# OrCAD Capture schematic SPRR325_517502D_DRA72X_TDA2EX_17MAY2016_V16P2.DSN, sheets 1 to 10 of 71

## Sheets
1 SH01 - TITLE PAGE: title: DRA72x/TDA2Ex EVM CPU Board; rev: D; company: TEXAS INSTRUMENTS INCORPORATED; note: 517502
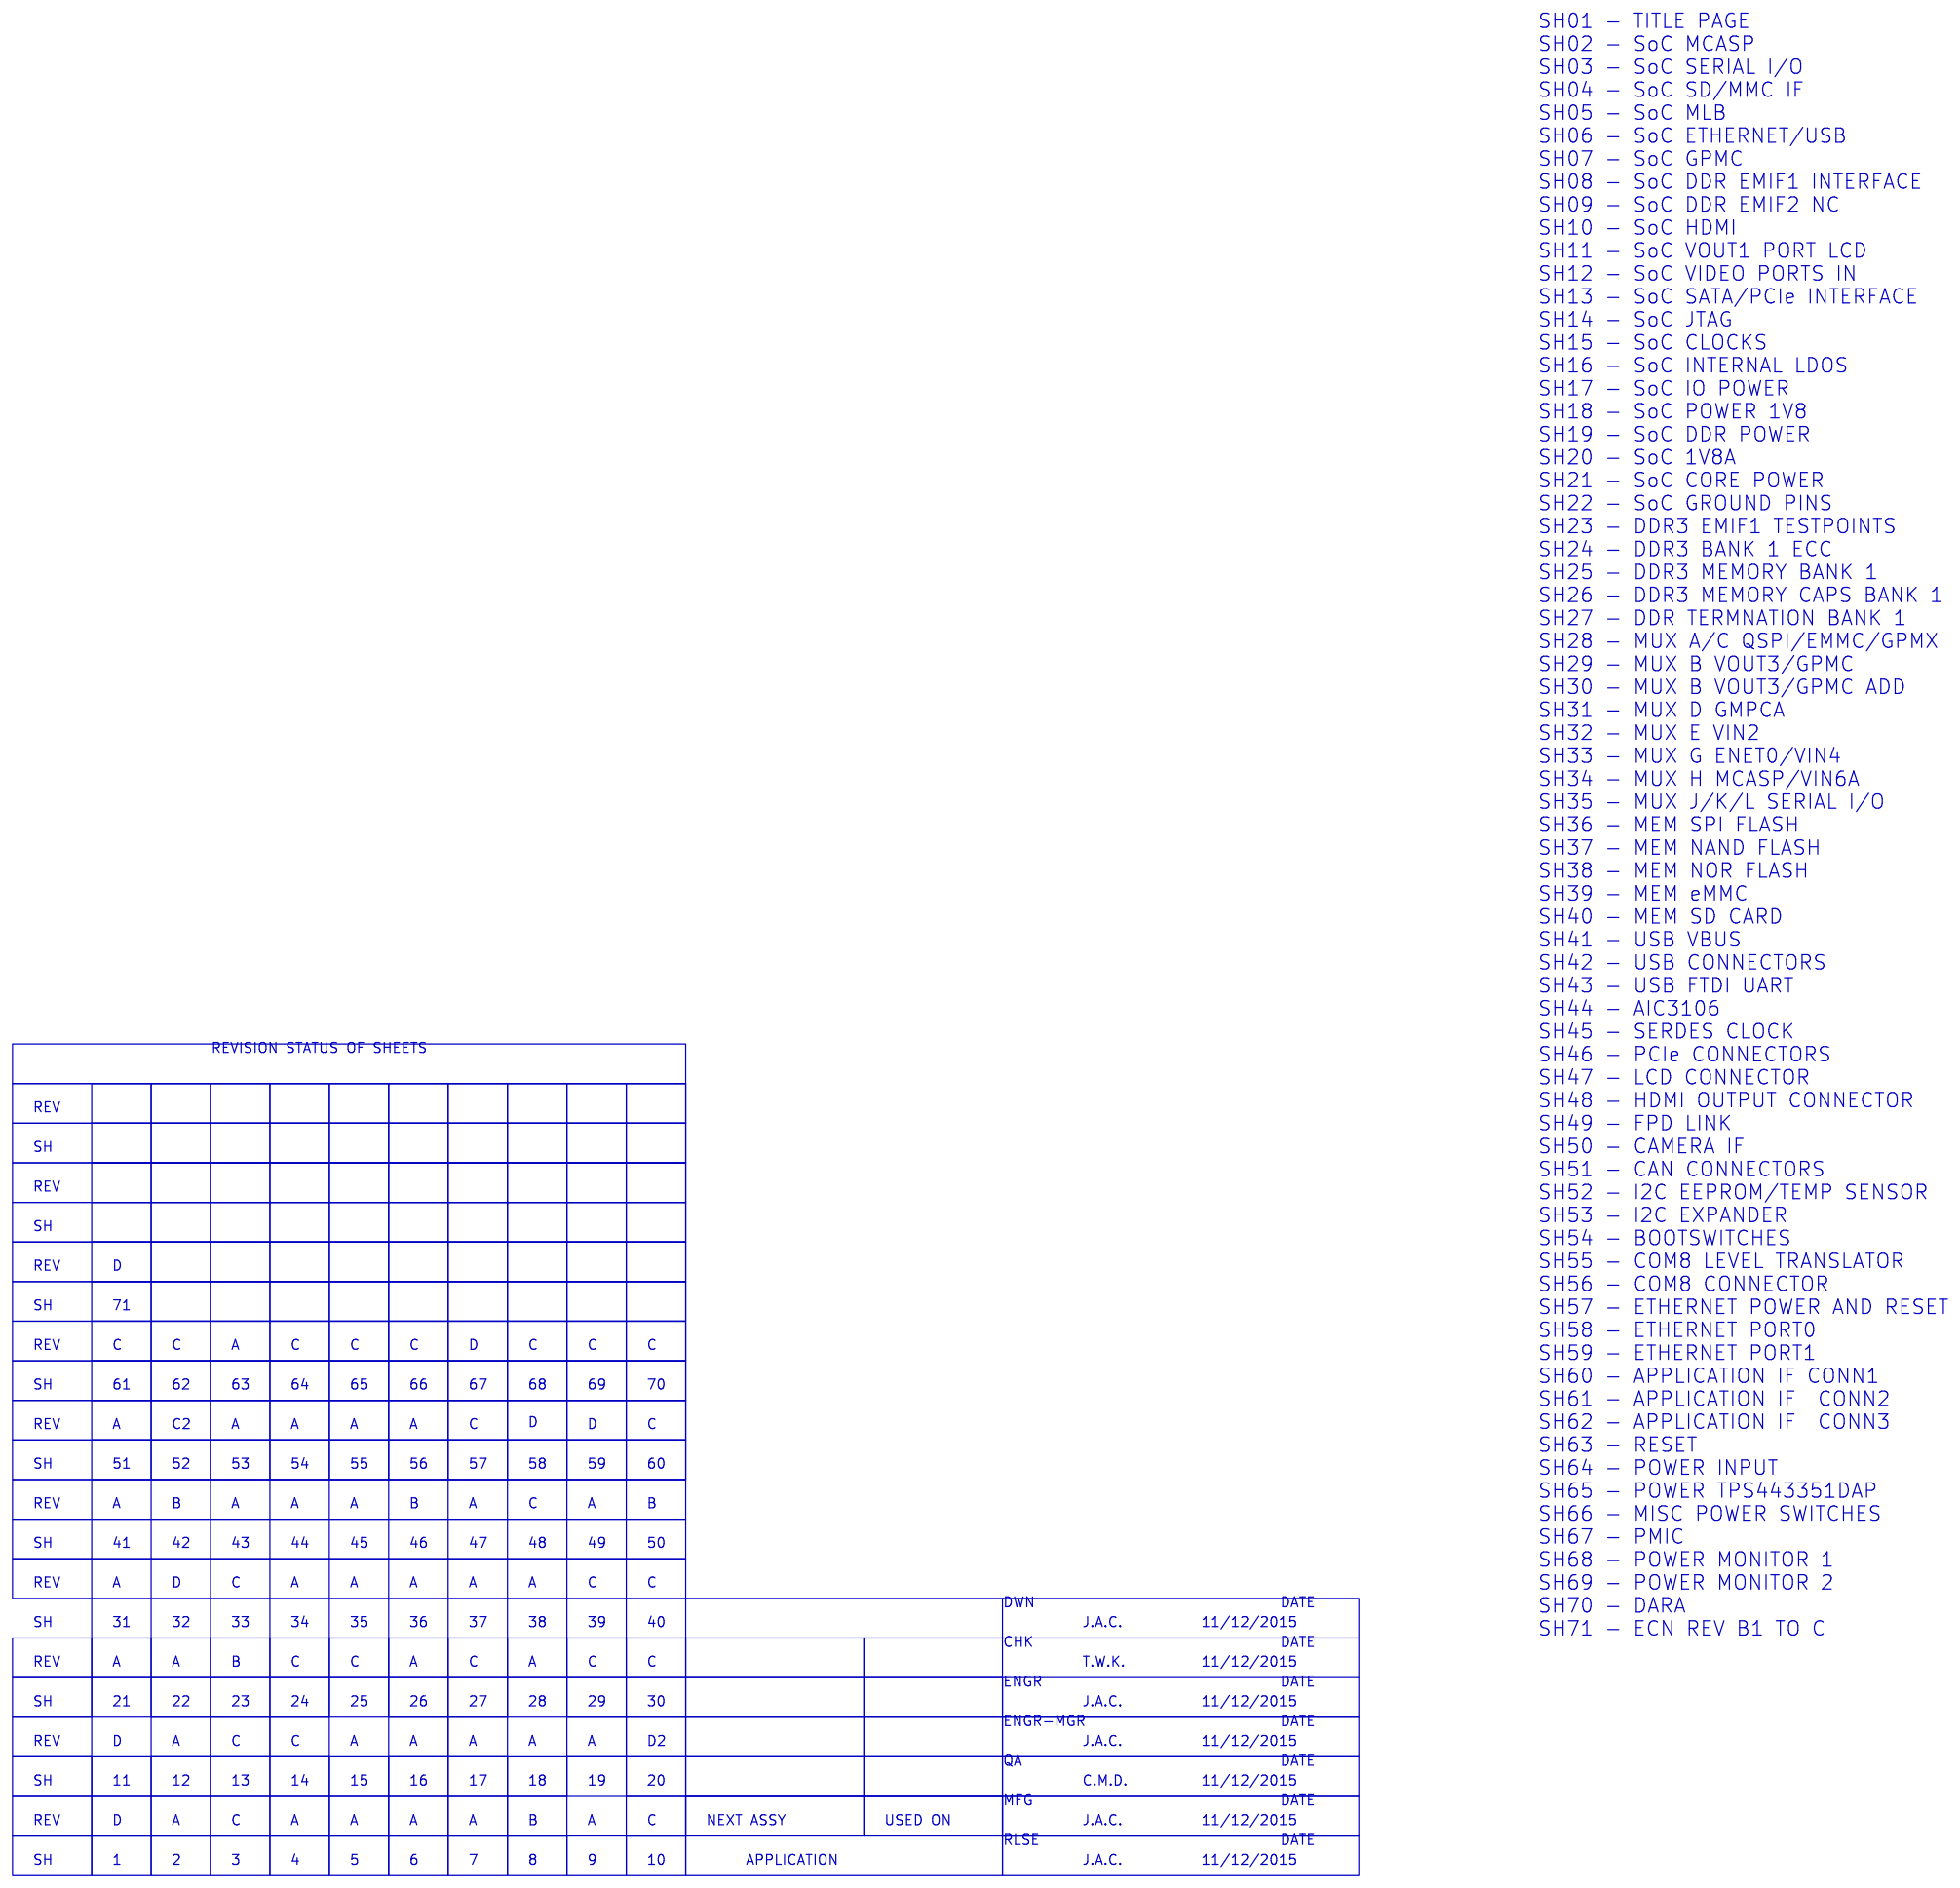
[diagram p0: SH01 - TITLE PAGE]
2 SH02 - SoC MCASP: size B; rev: A
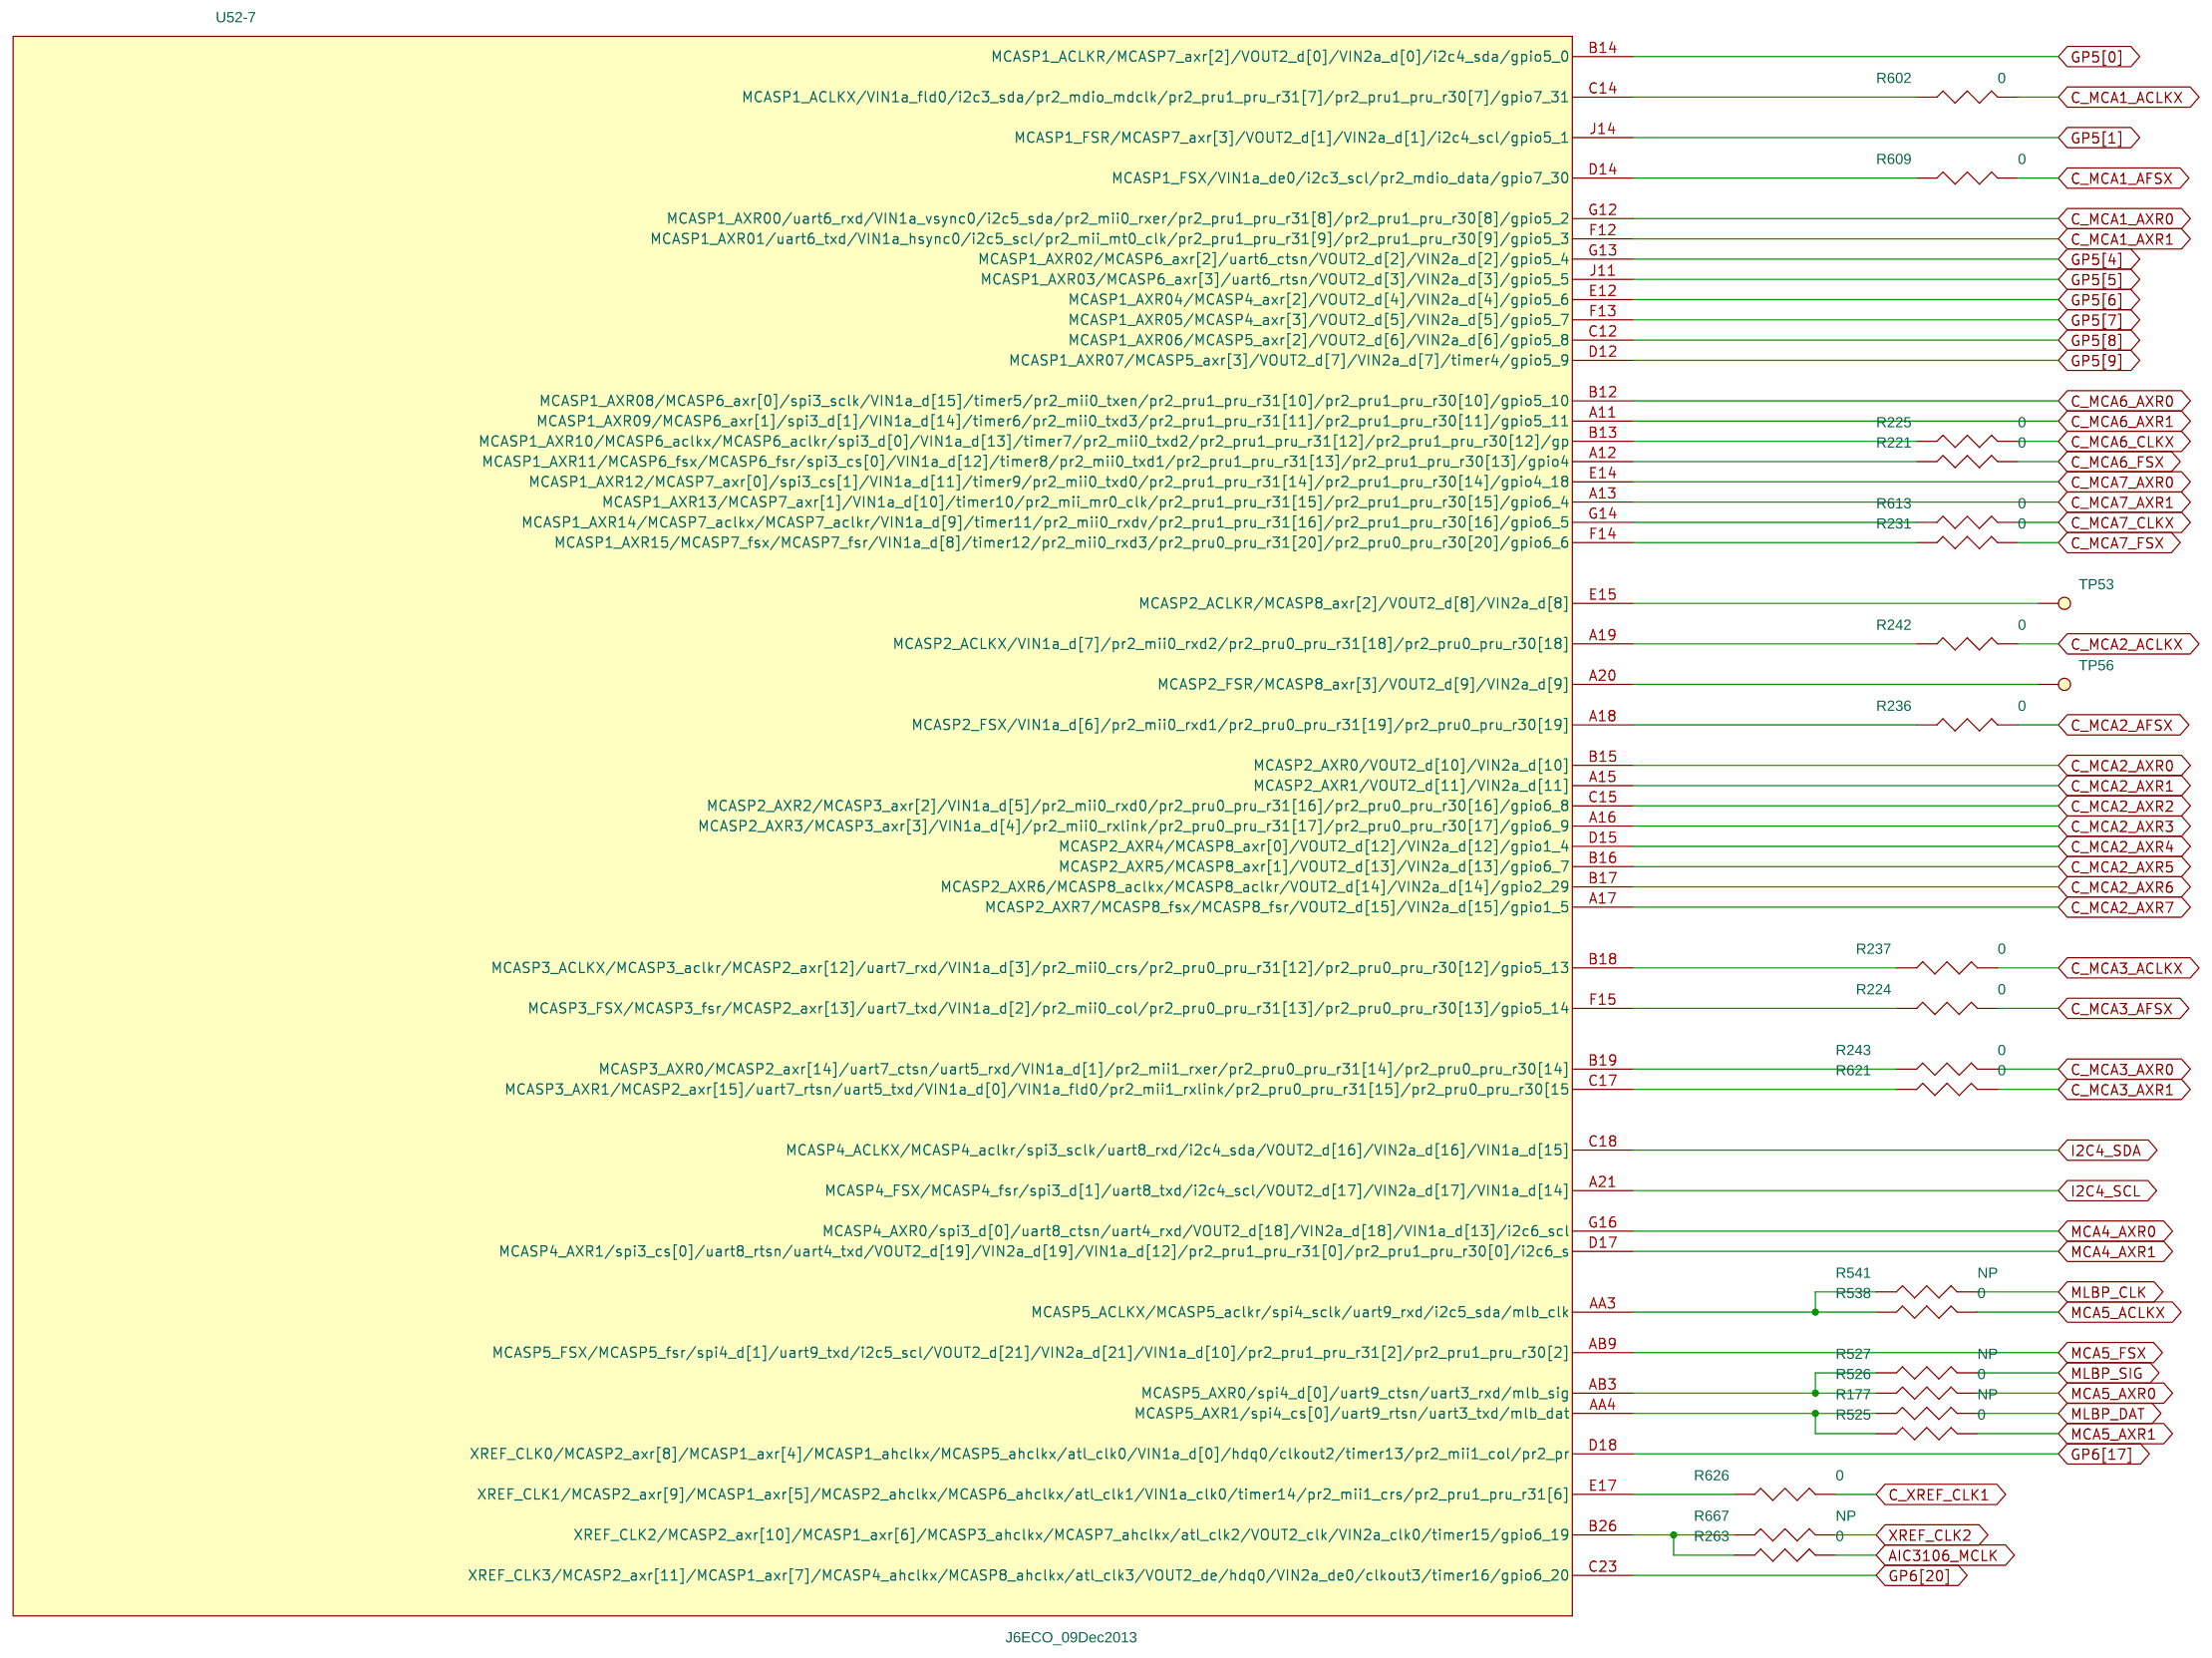
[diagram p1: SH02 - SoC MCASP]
3 SH05 - SoC MLB: size B; rev: A
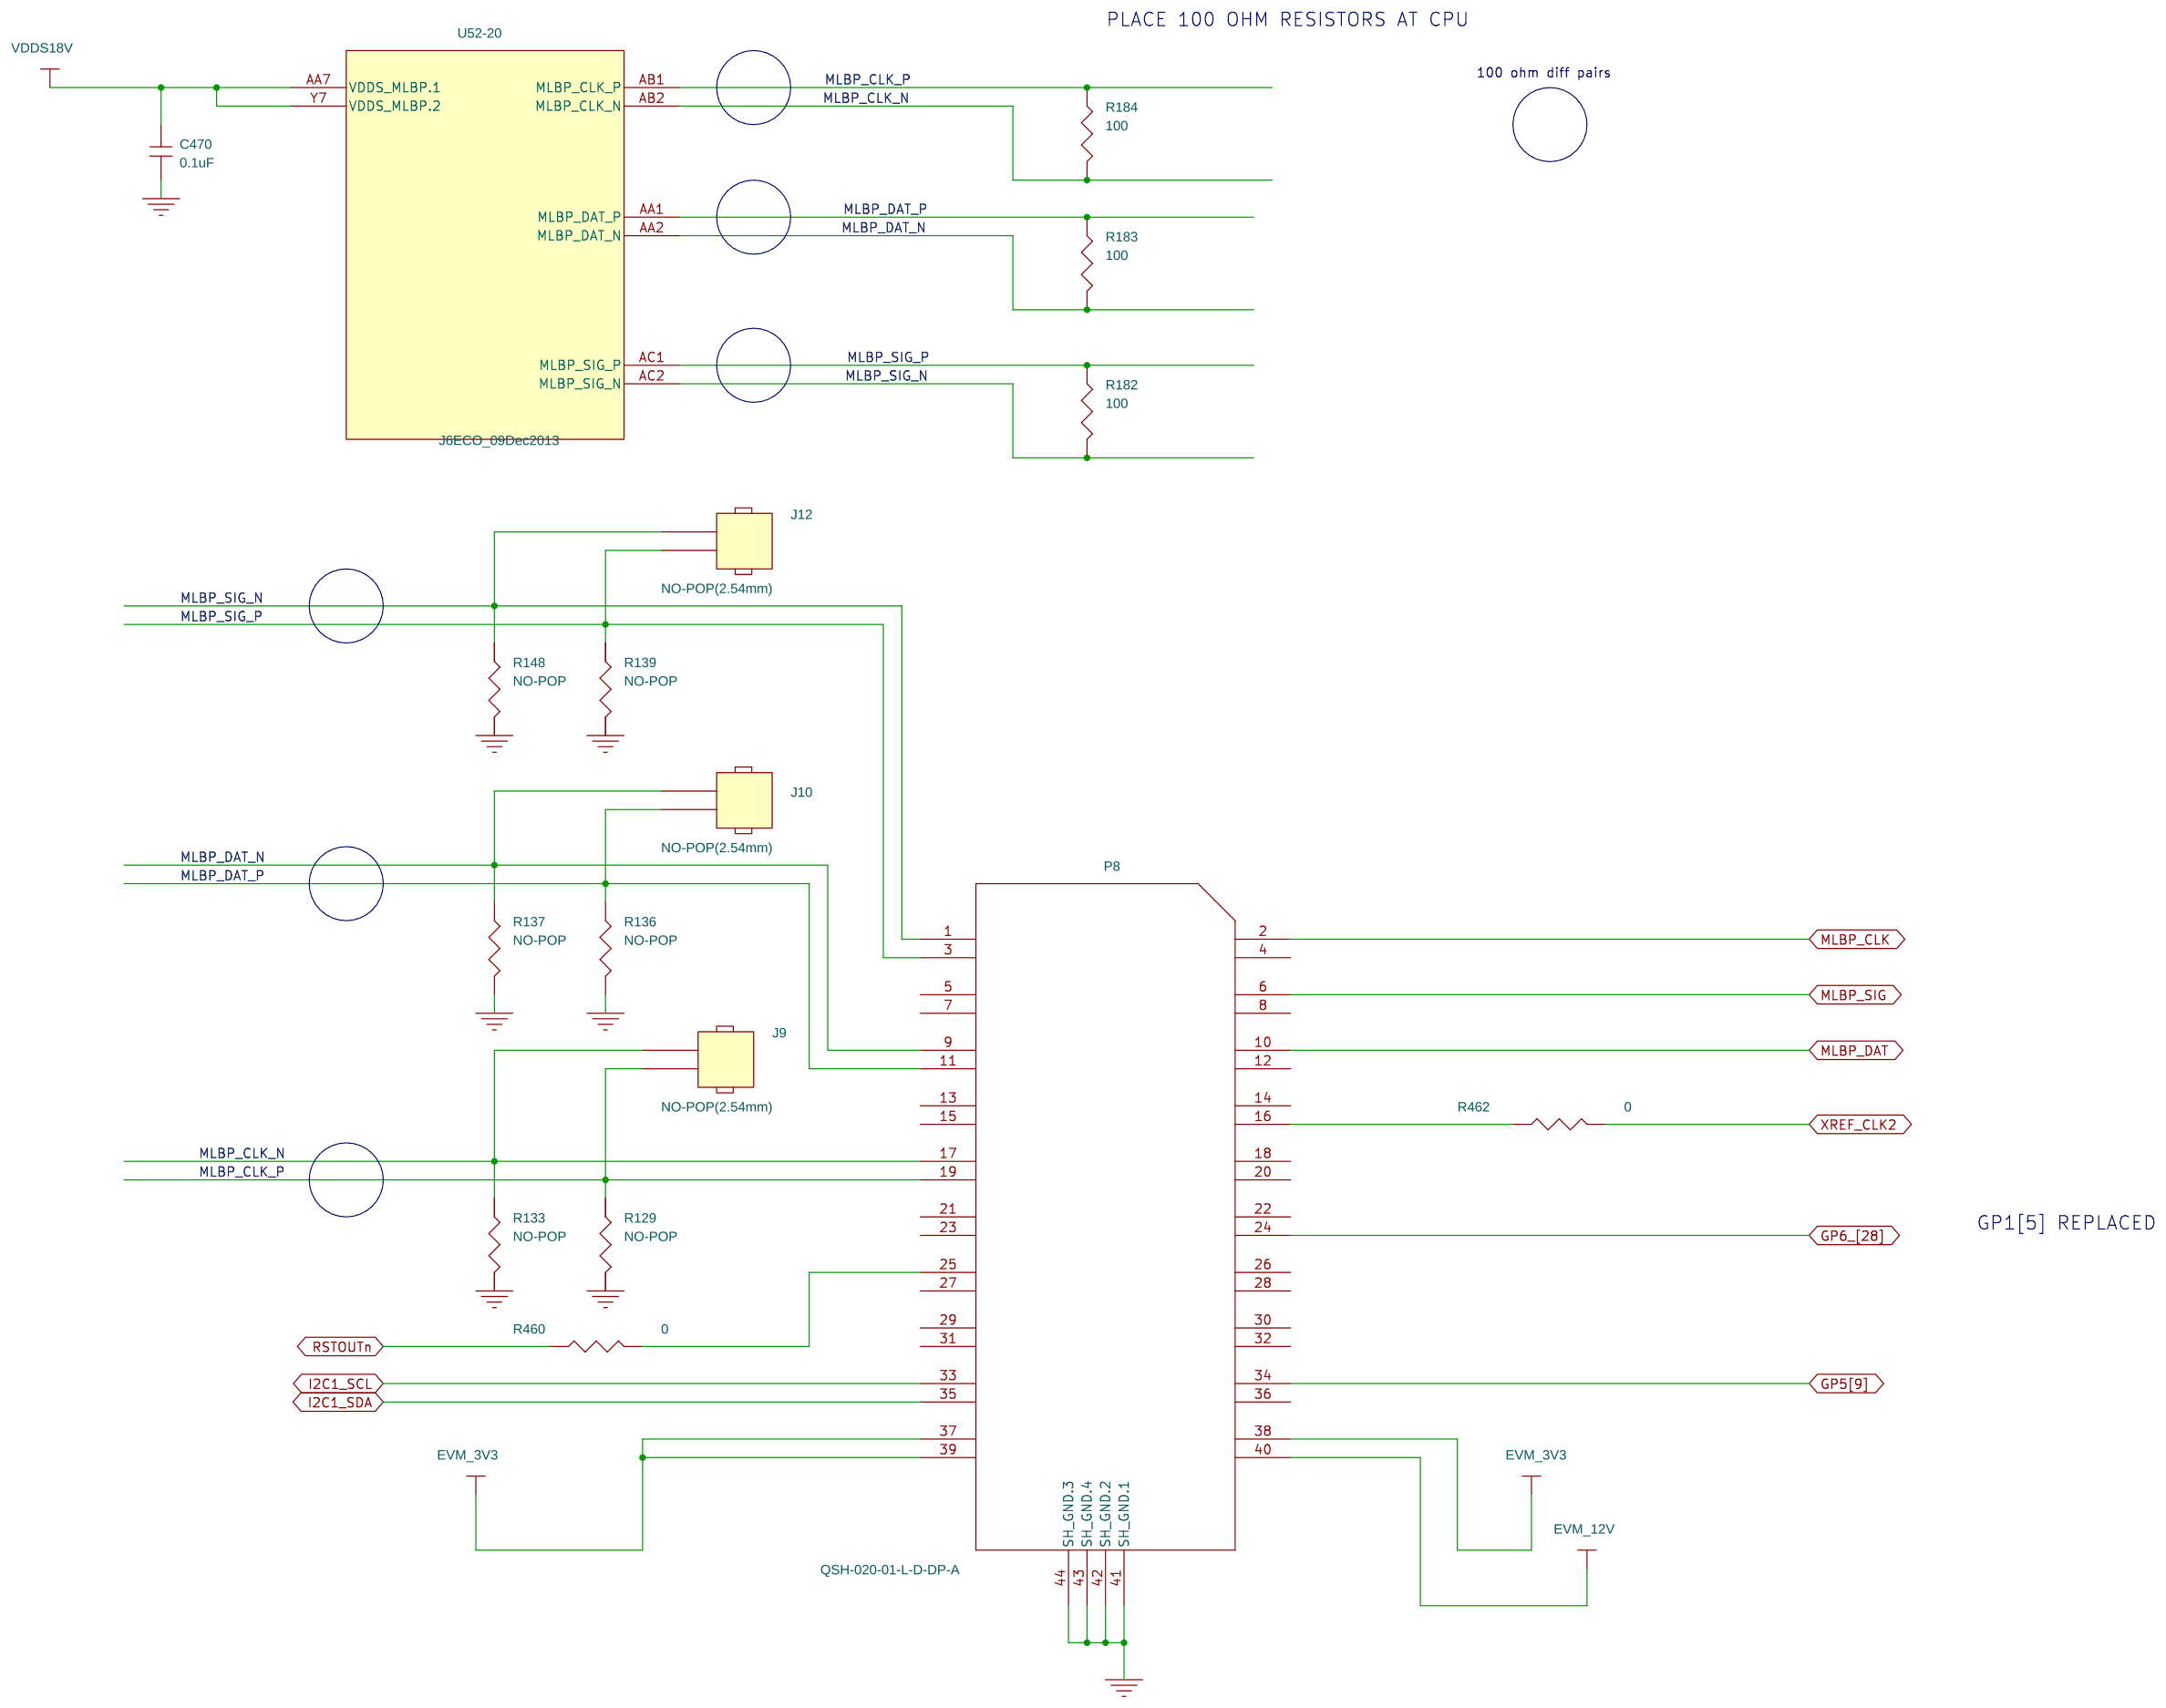
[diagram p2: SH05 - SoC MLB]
4 SH07 - SoC GPMC: size B; rev: A
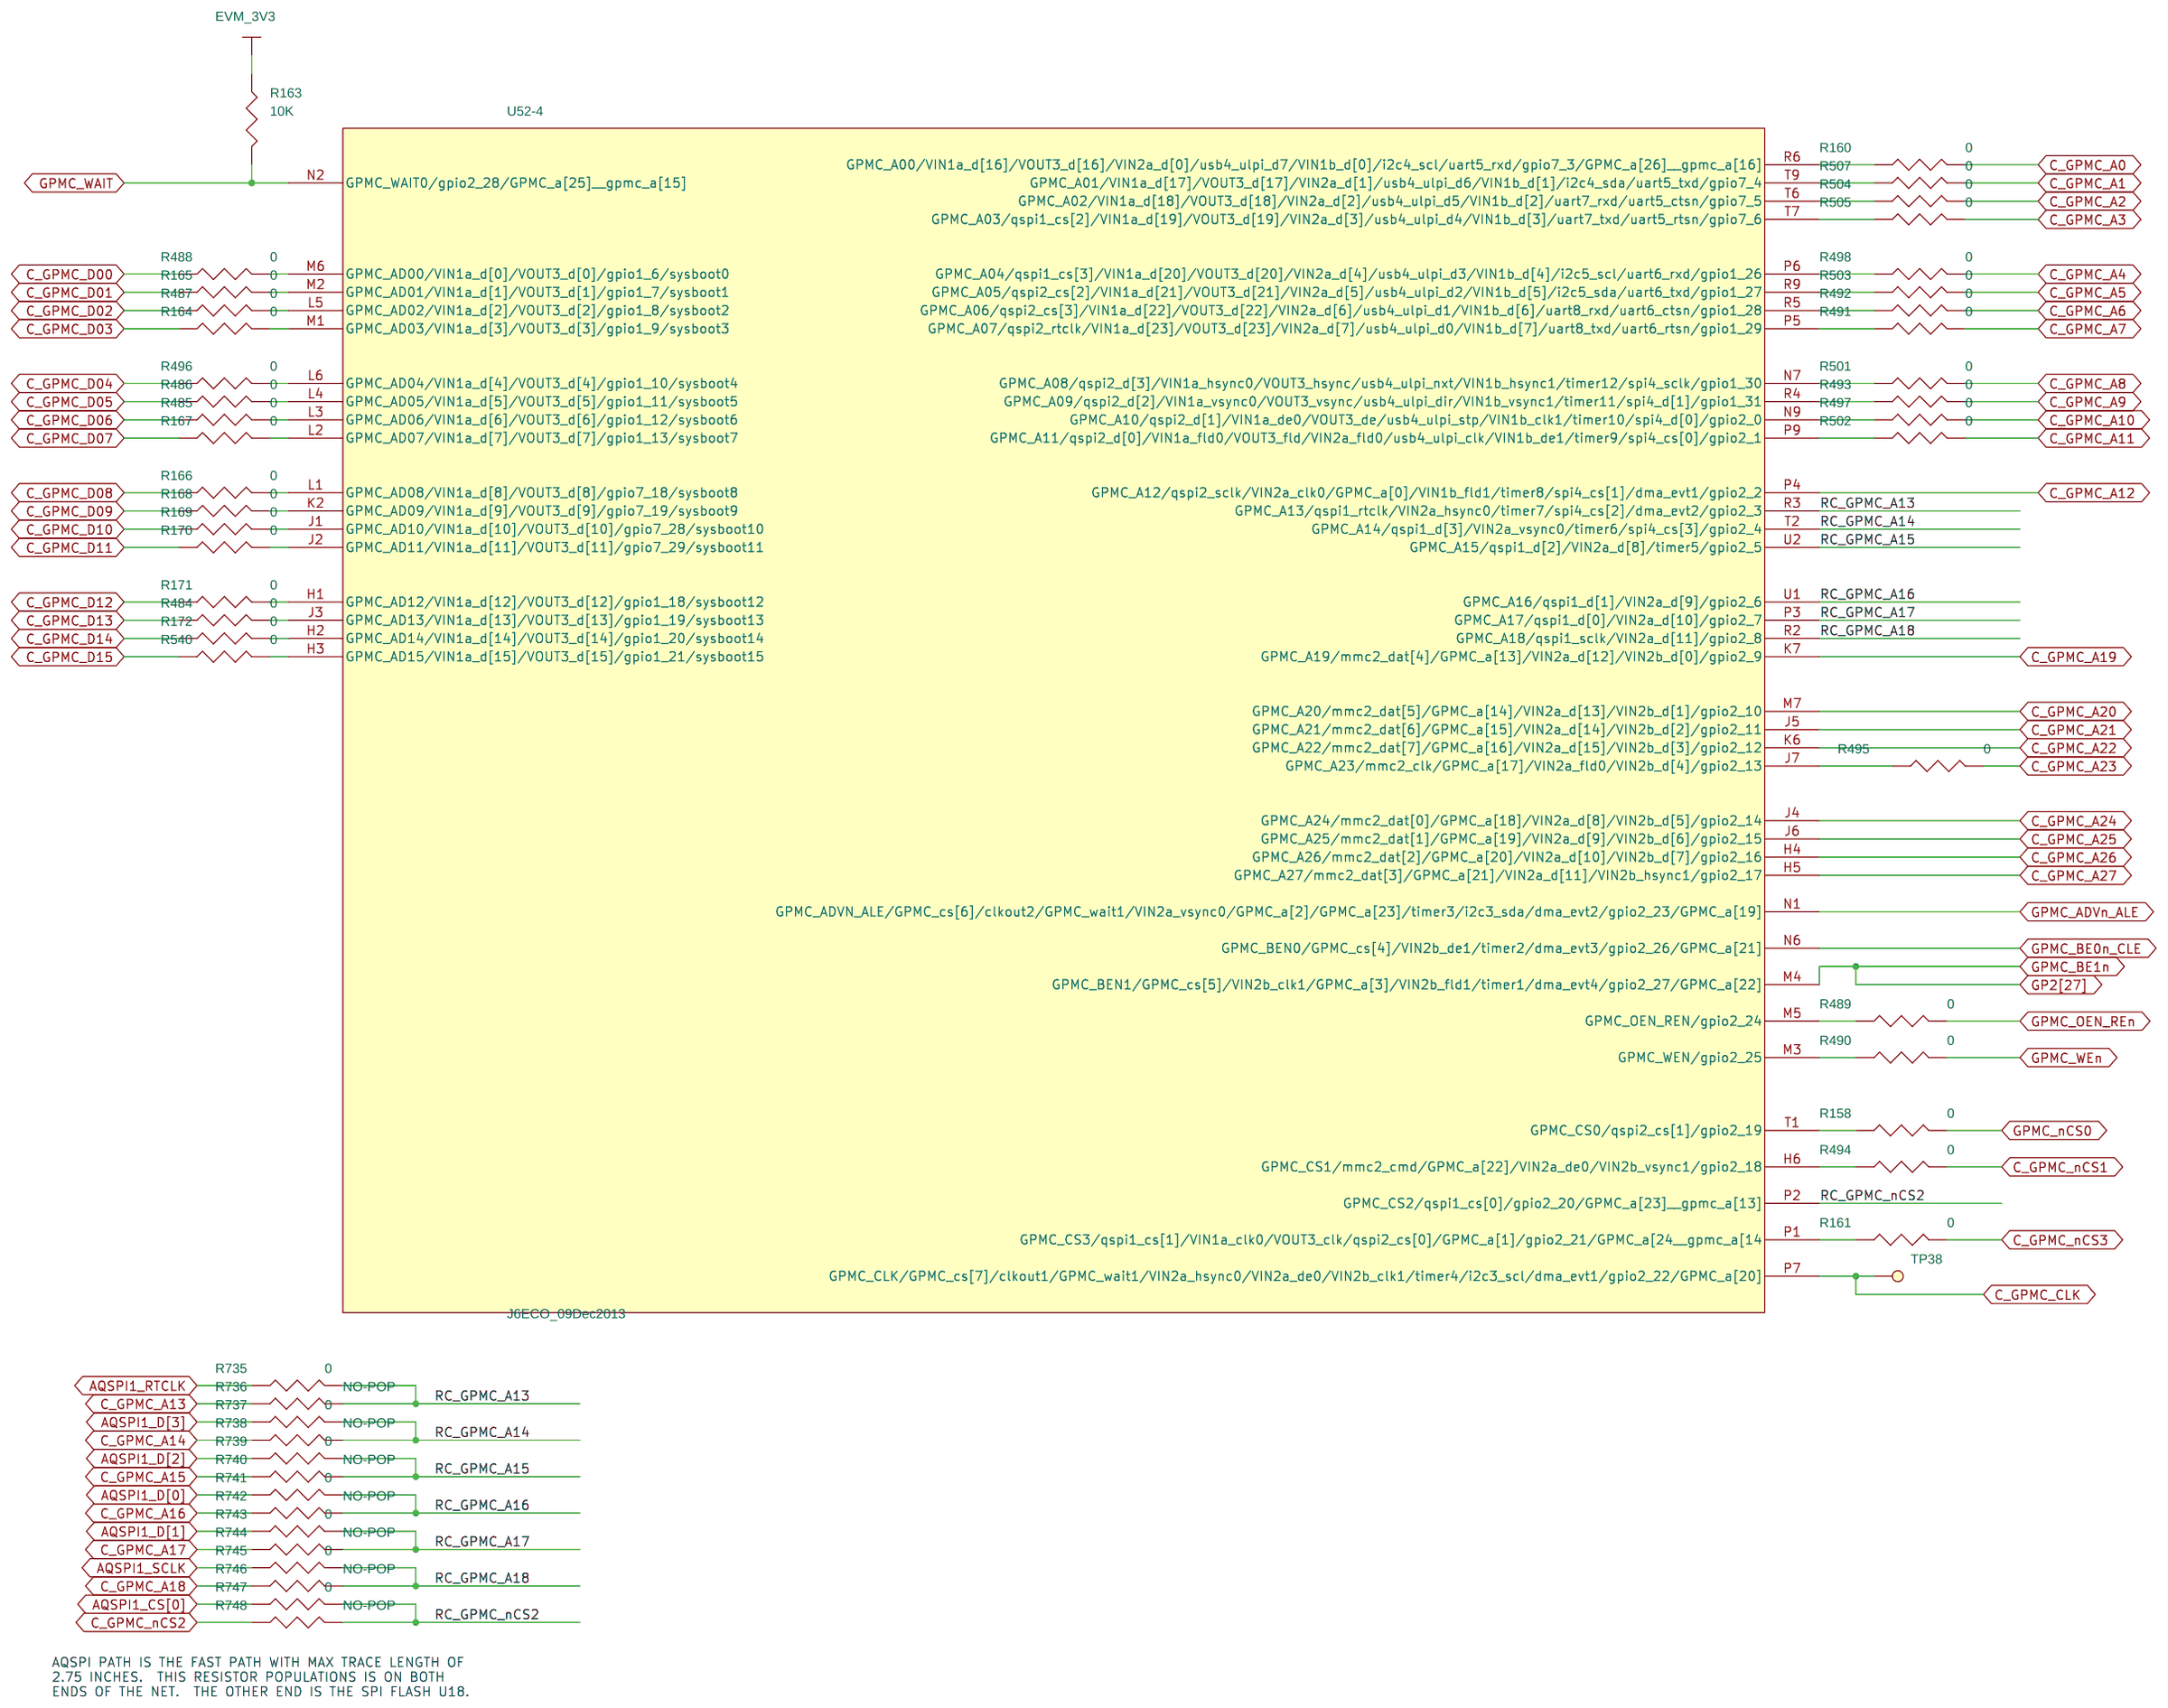
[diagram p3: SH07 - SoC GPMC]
5 SH08 - SoC DDR EMIF1 INTERFACE: size B; rev: B
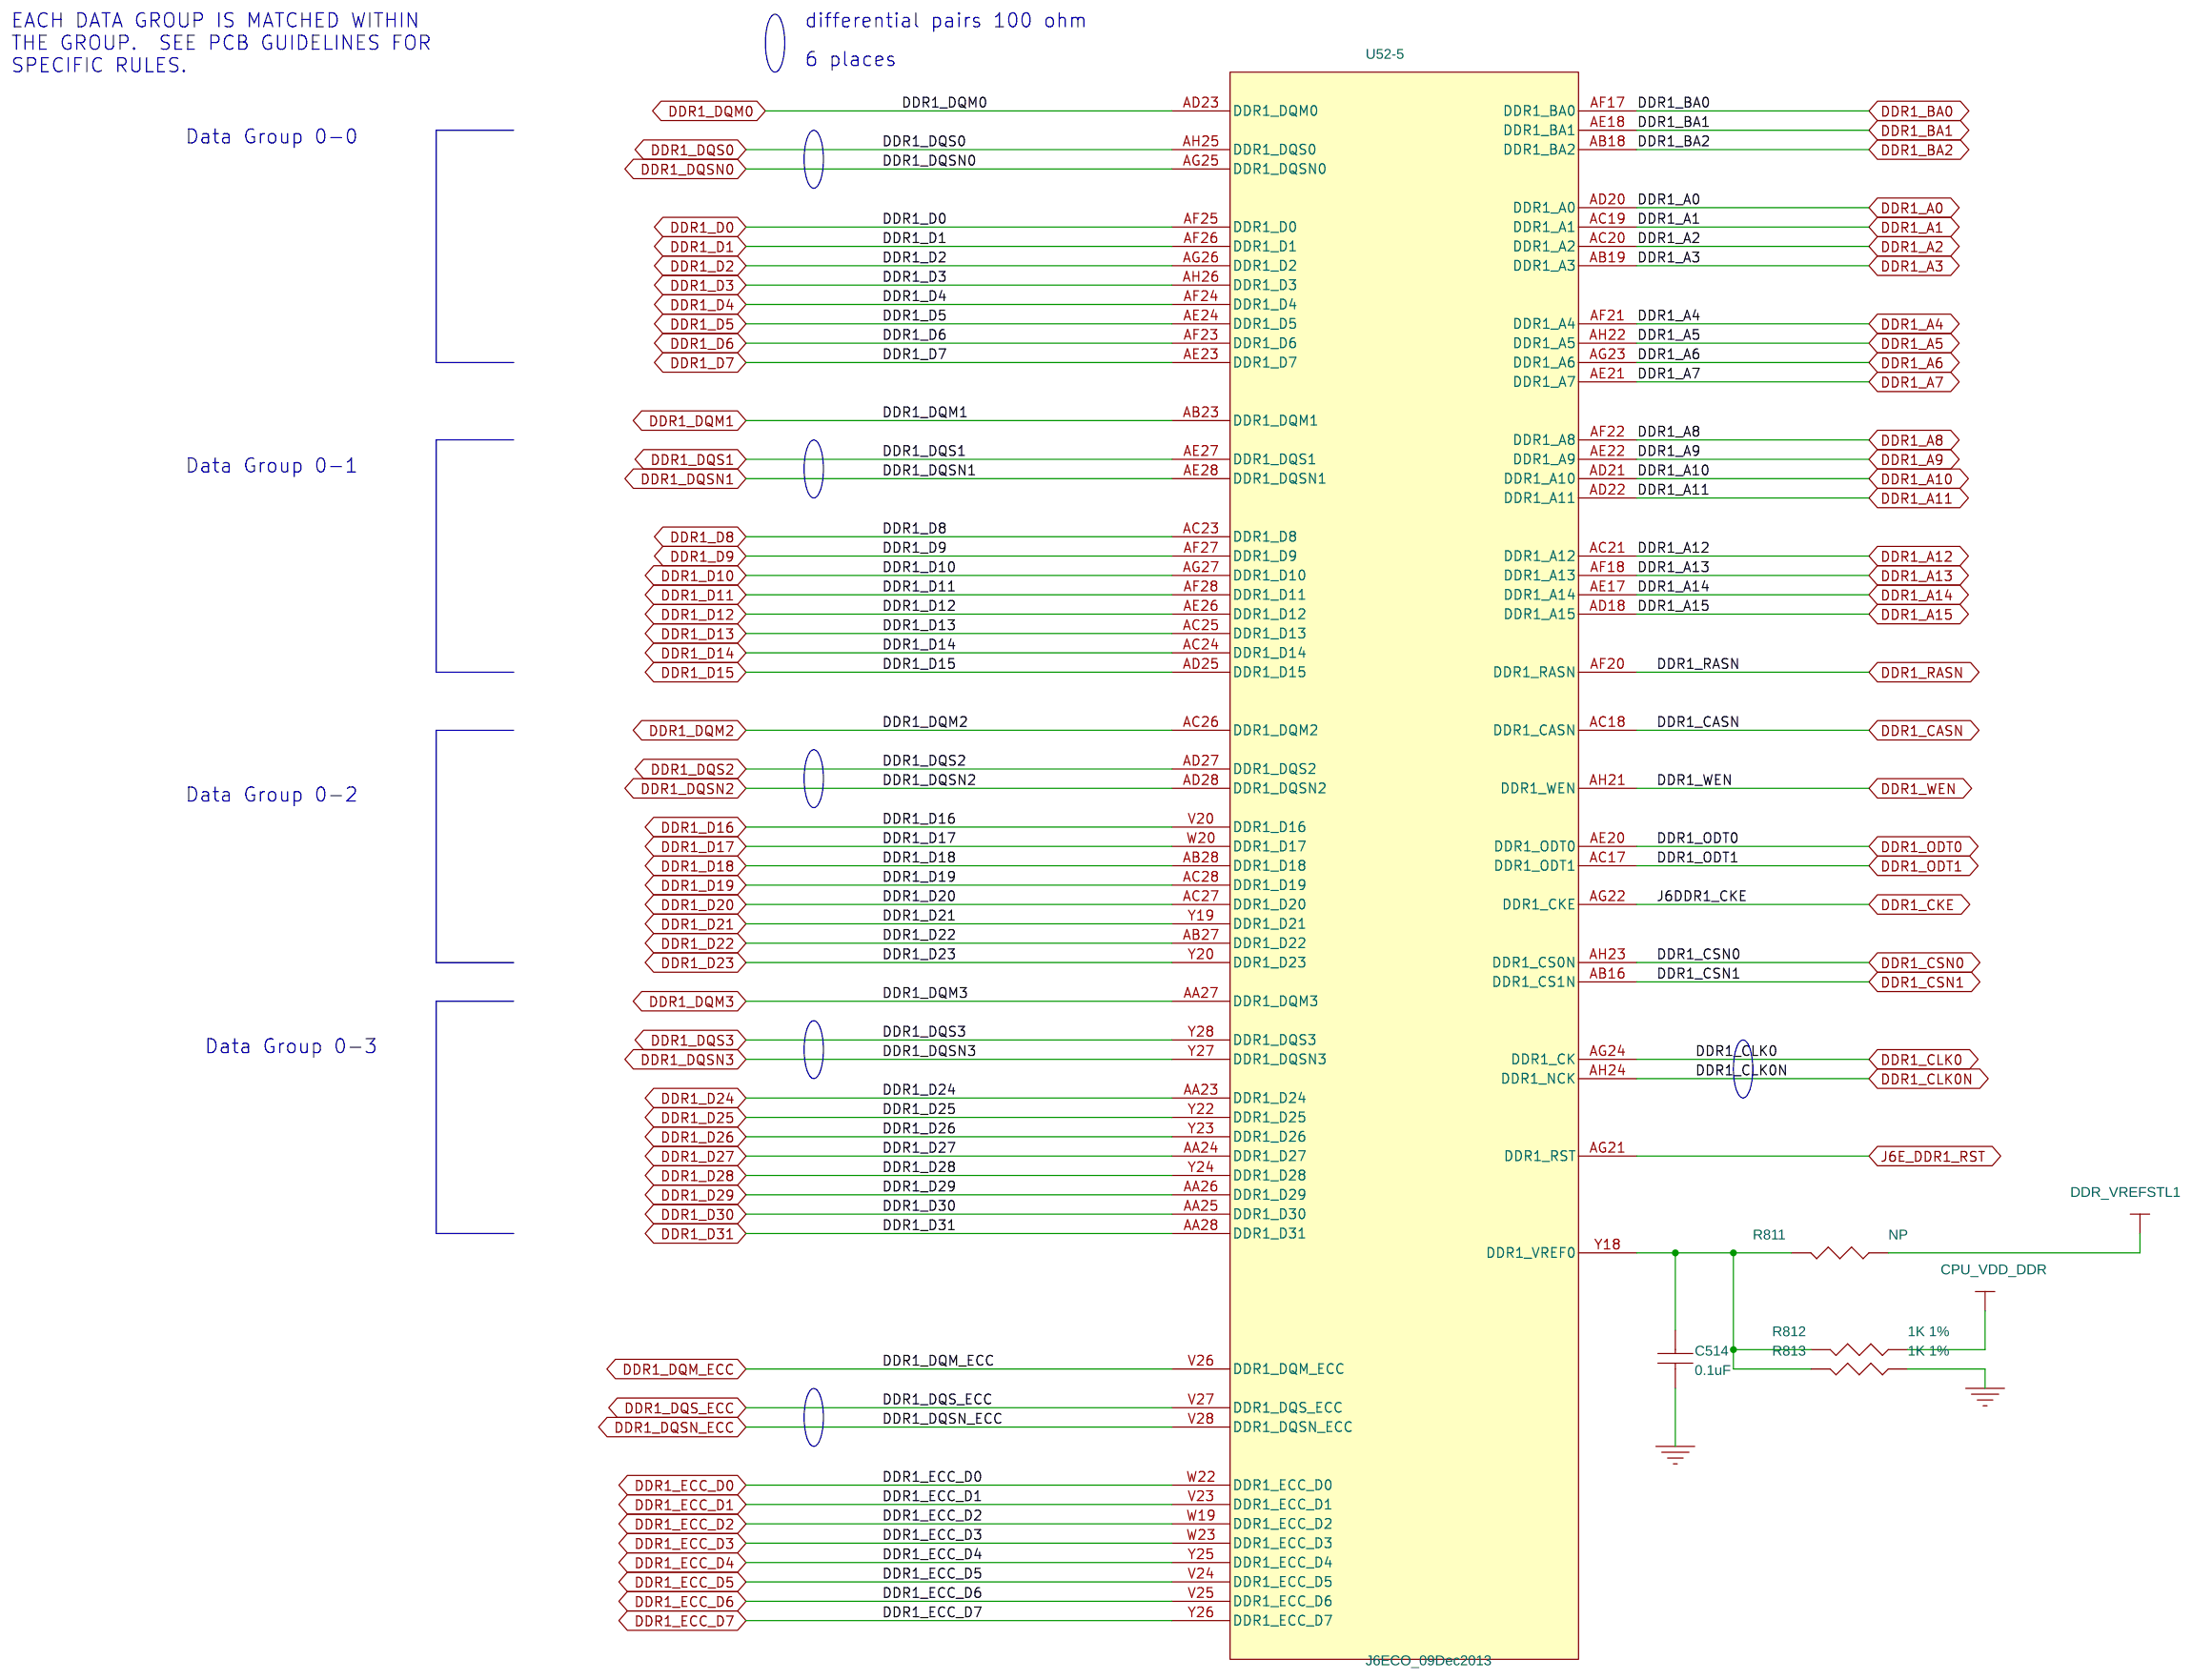
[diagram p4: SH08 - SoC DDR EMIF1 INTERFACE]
6 SH09 - SoC DDR EMIF2 NC: size B; rev: A
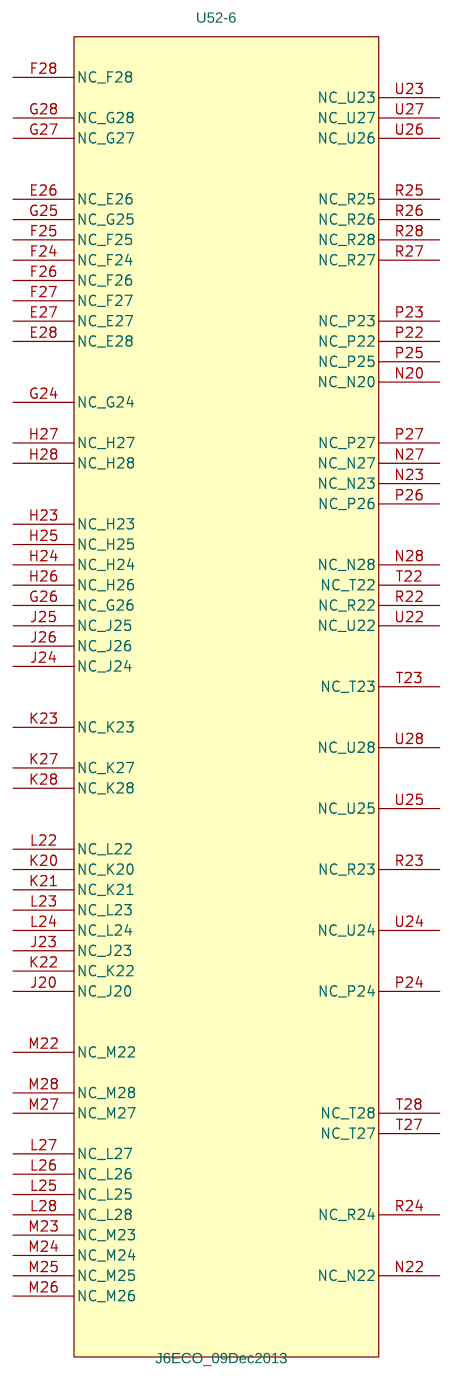
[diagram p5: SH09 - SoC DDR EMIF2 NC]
7 SH10 - SoC HDMI: size B; rev: C
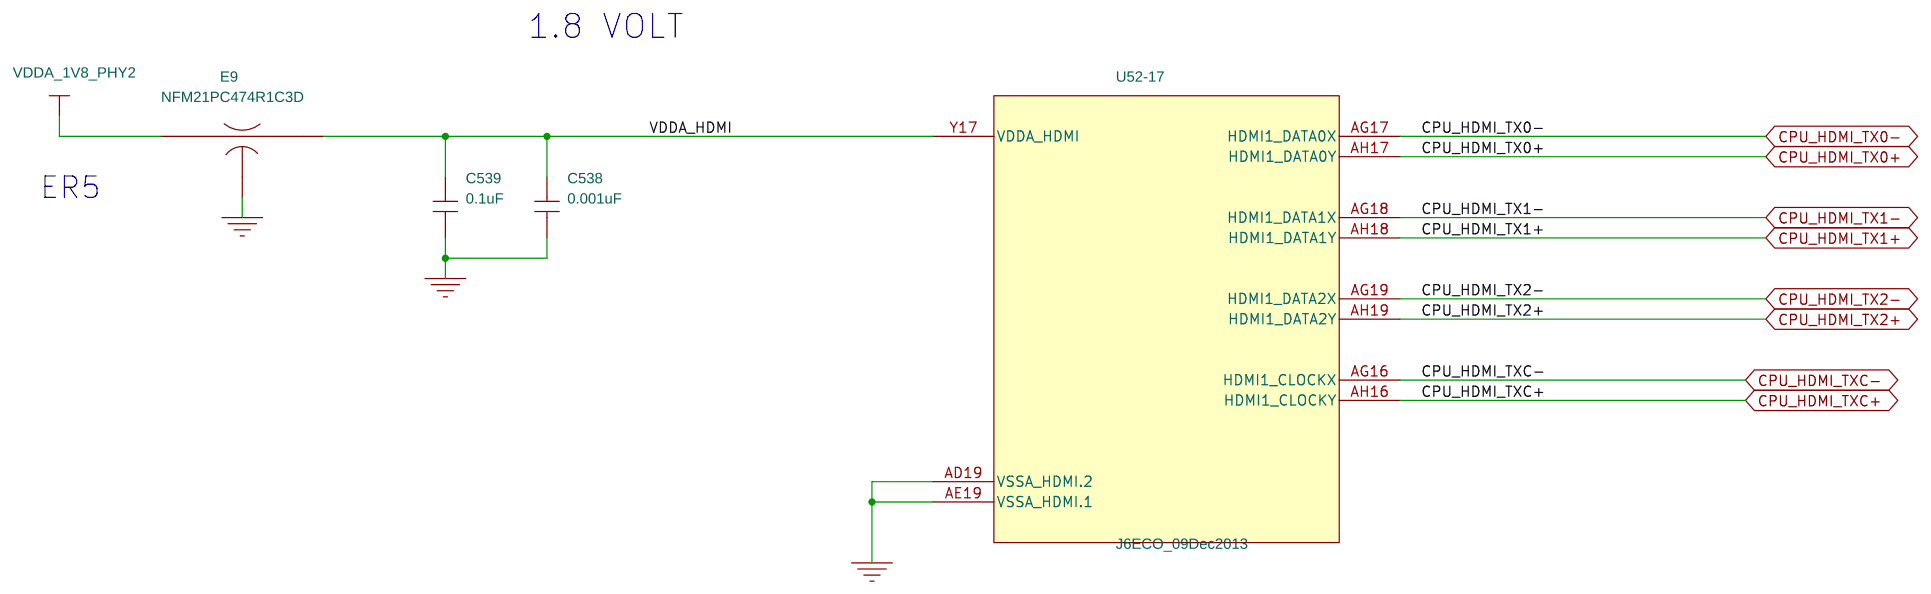
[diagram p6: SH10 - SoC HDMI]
8 SH11 - SoC VOUT1 PORT LCD: size B
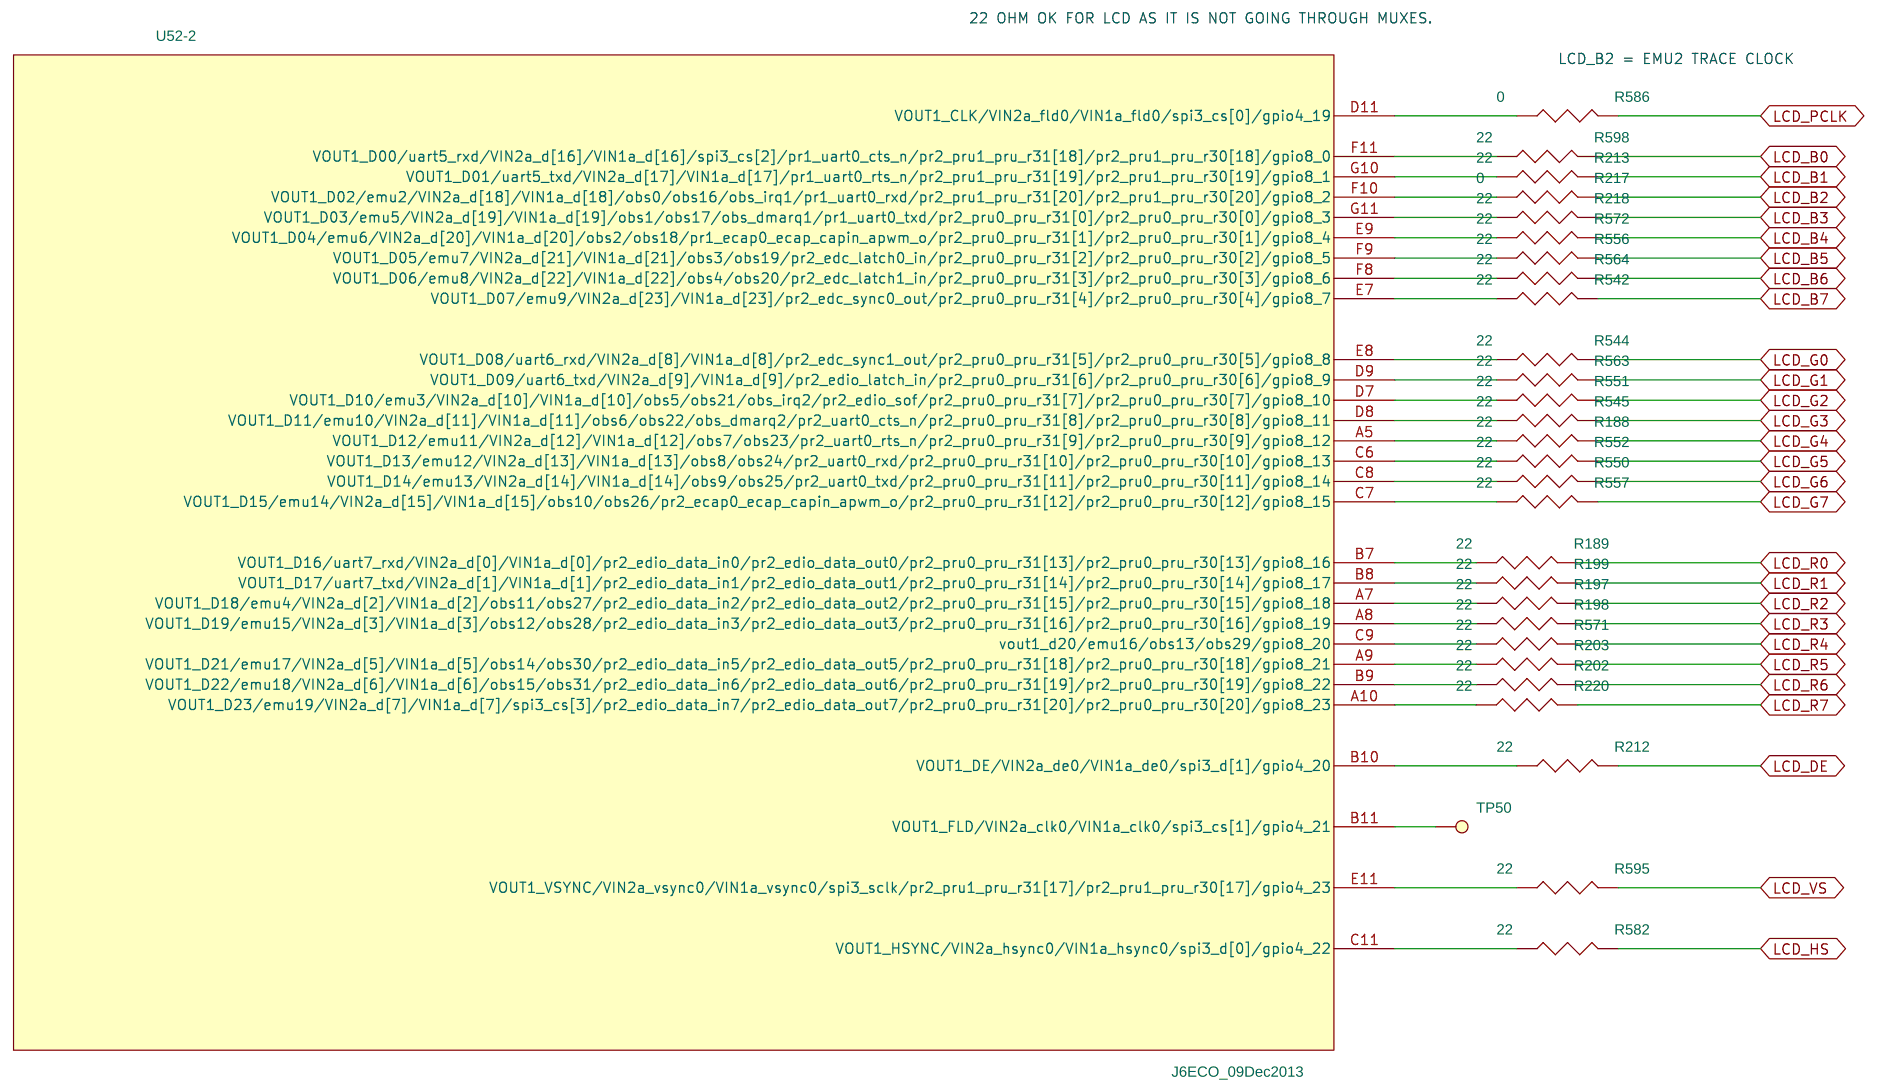
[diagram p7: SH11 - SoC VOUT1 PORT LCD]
9 SH12 - SoC VIDEO PORTS IN: size B; rev: A
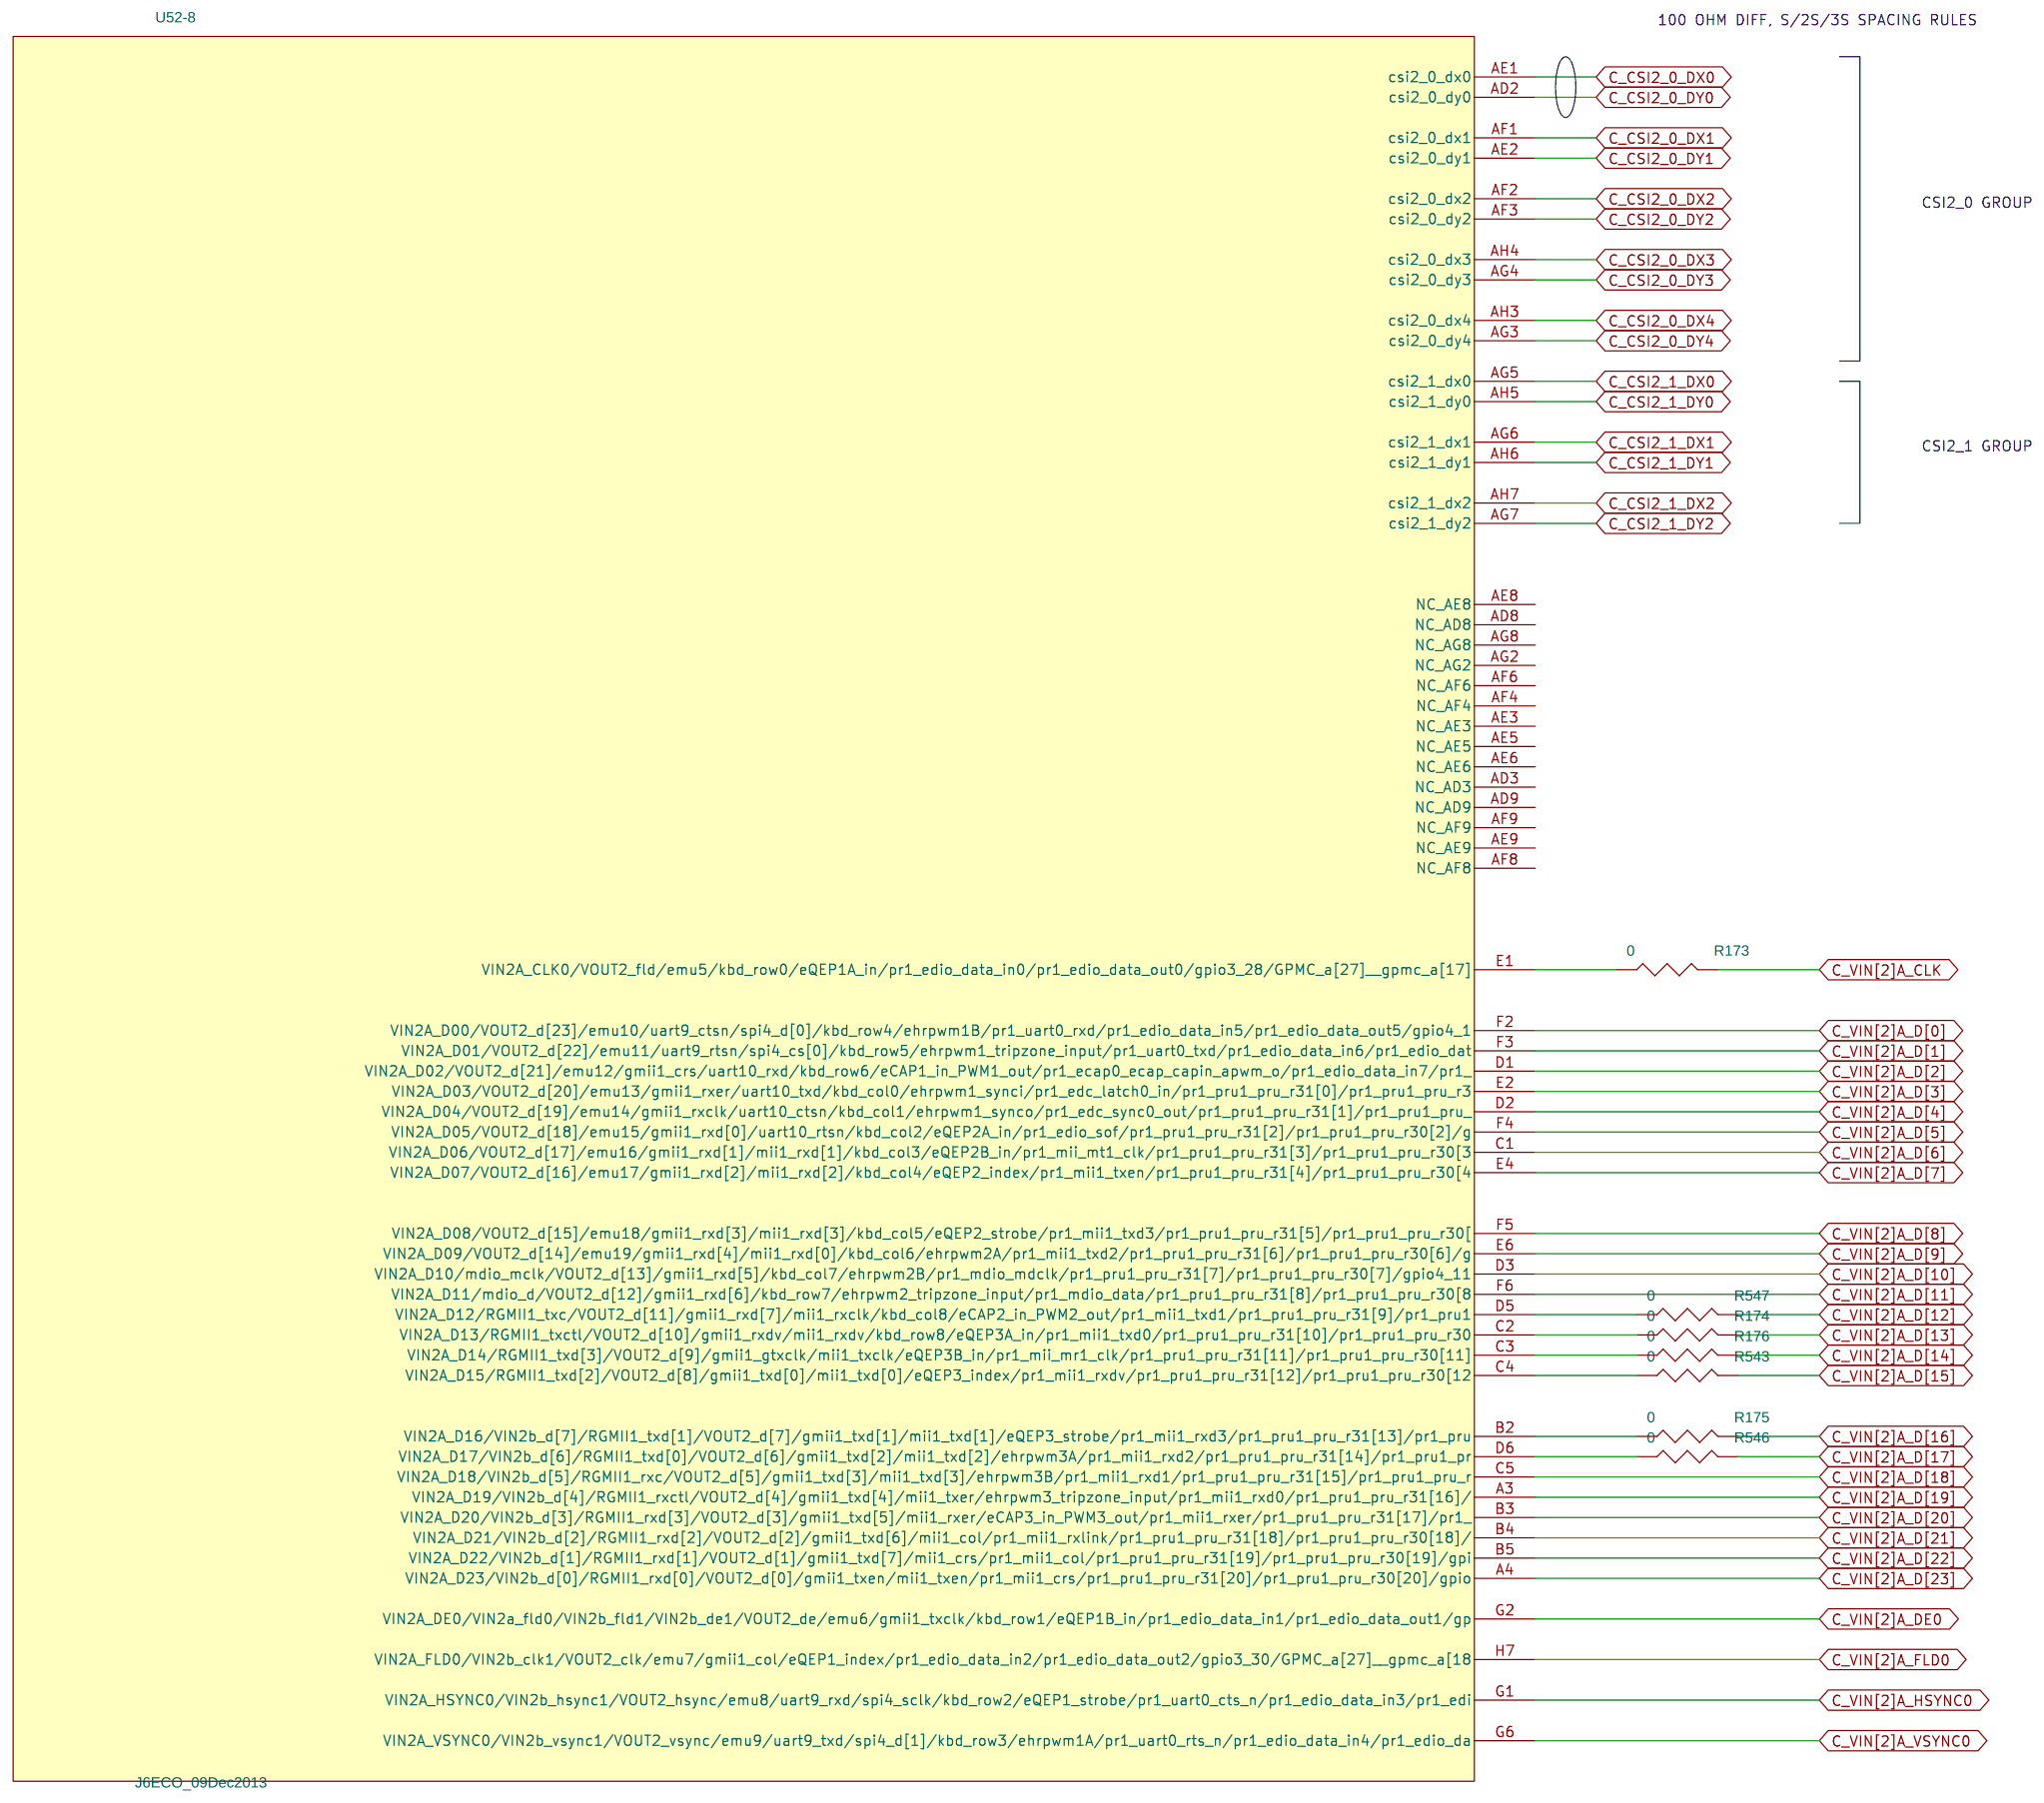
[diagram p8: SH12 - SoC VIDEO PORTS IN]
10 SH14 - SoC JTAG: size B; rev: C
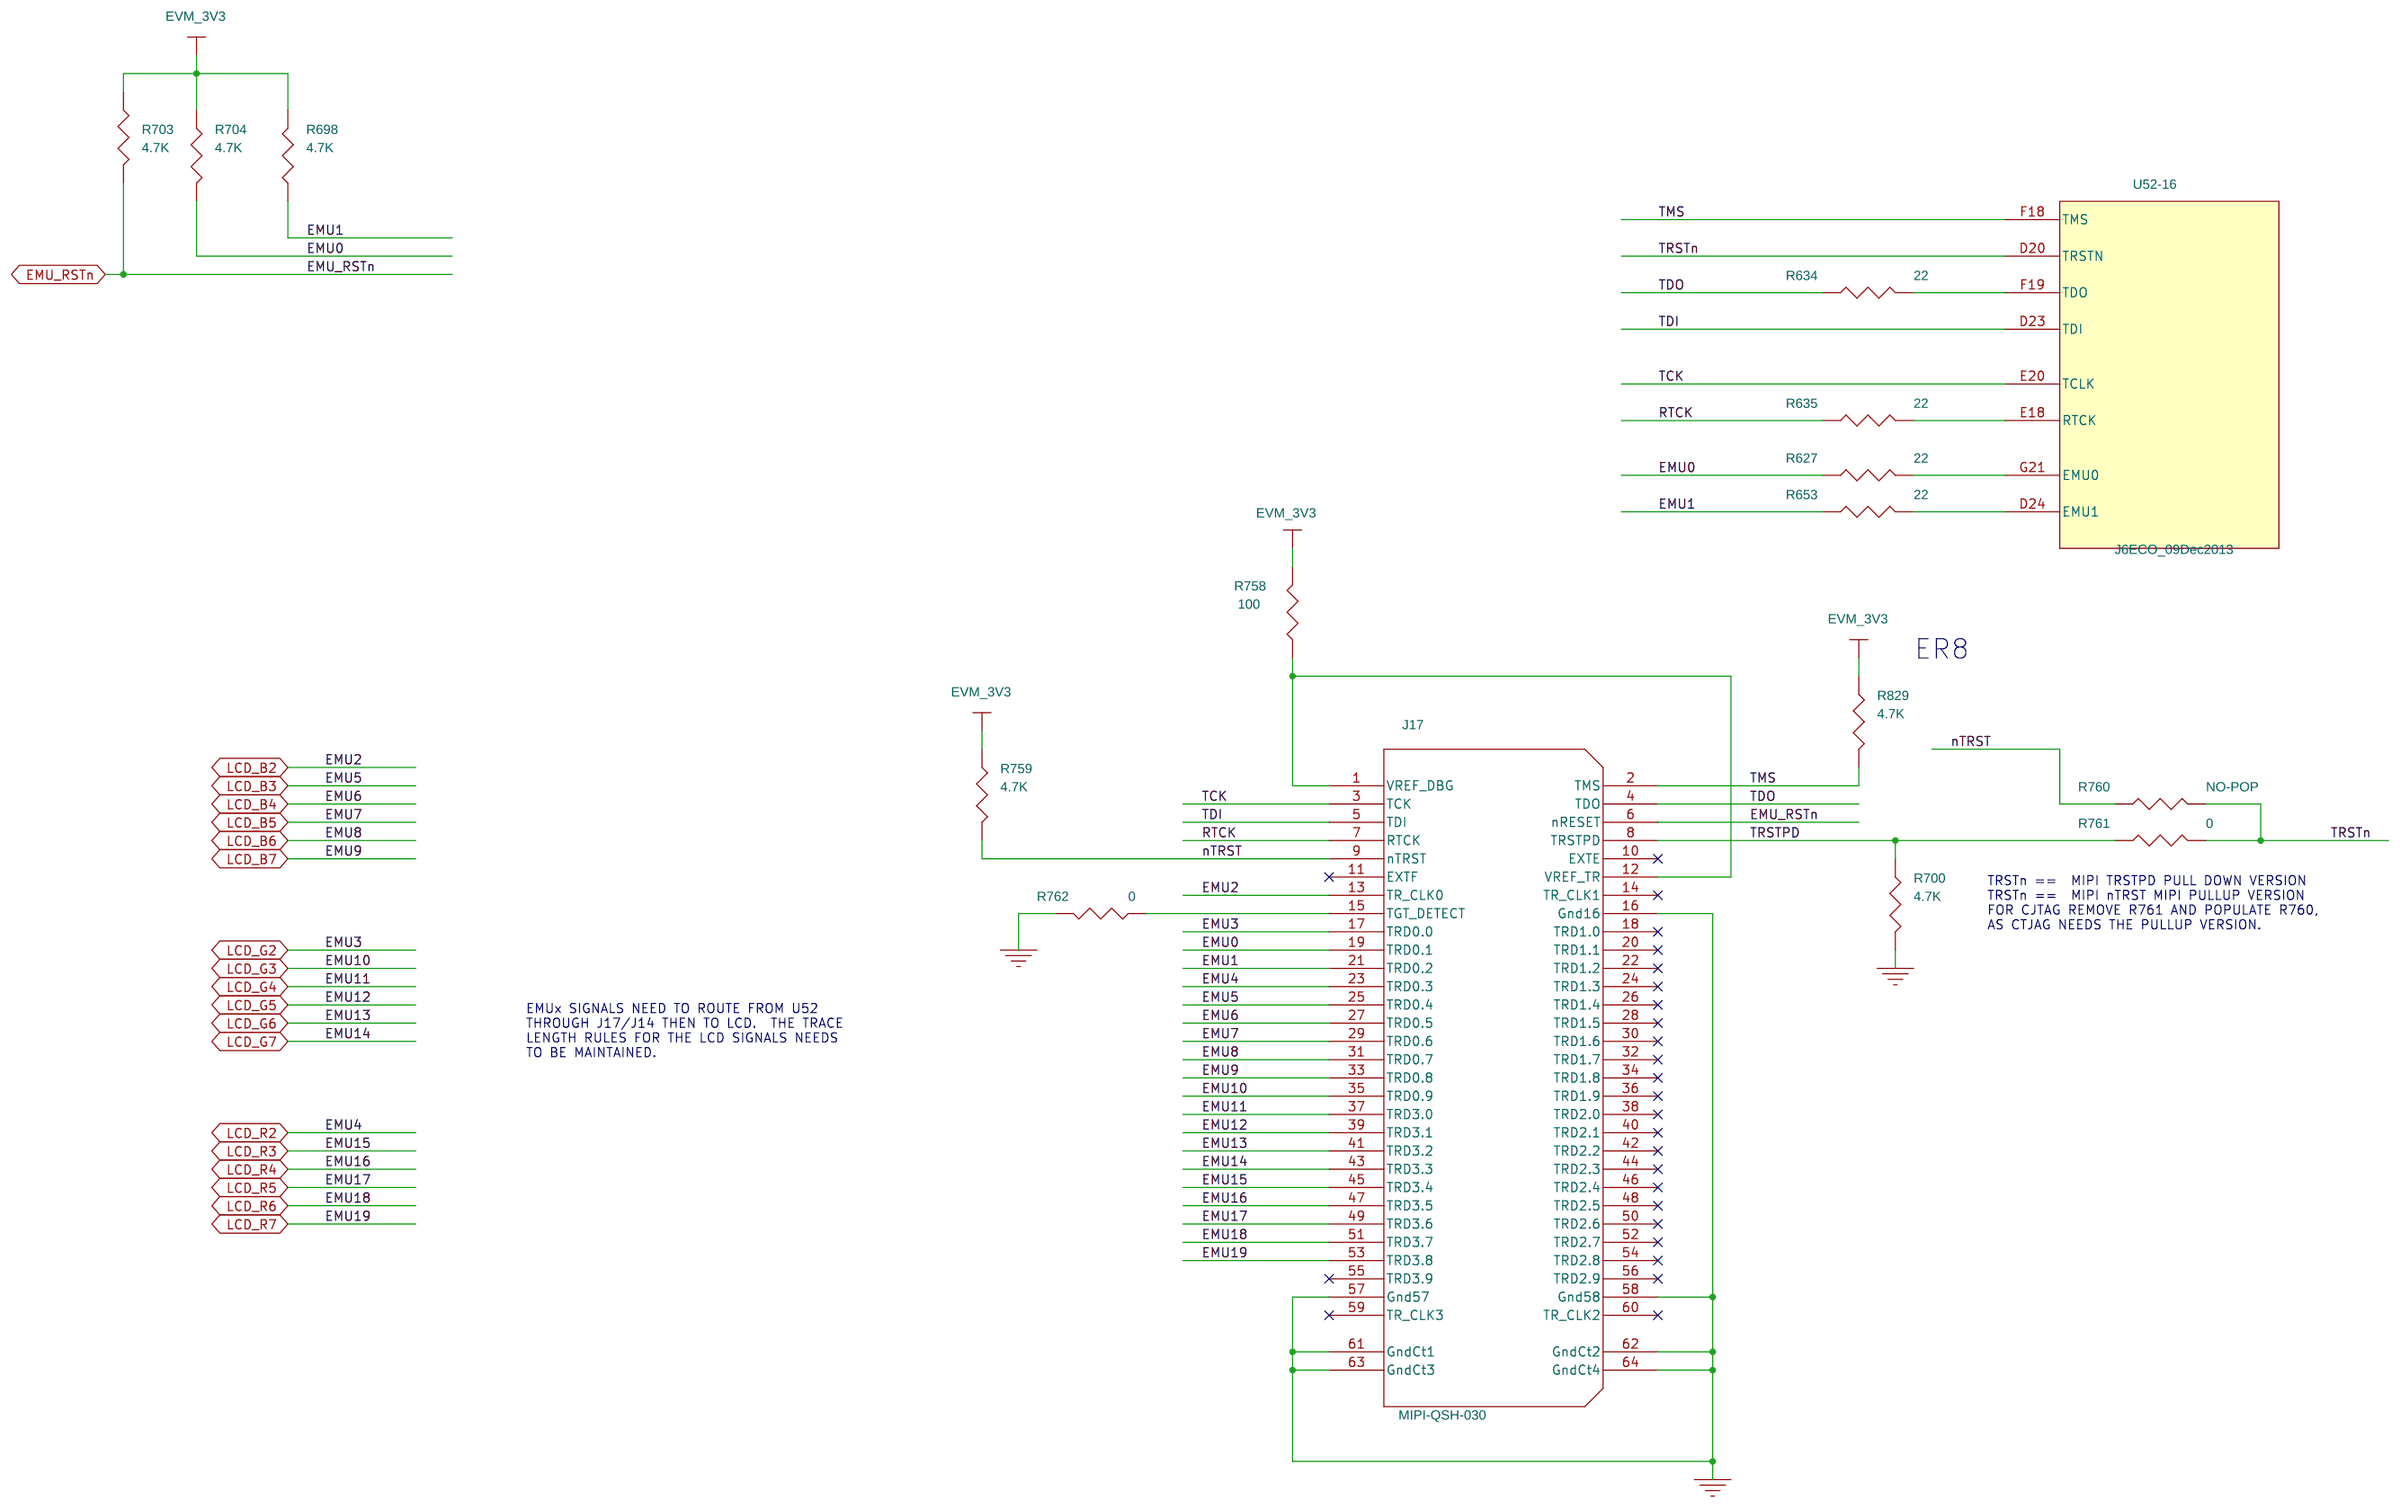
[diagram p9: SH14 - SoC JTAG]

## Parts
sheet SH02 - SoC MCASP
R177  NP  [r402-25]
R221  0  [r201-6p6spc]
R224  0  [r201-6p6spc]
R225  0  [r201-6p6spc]
R231  0  [r201-6p6spc]
R236  0  [r201-6p6spc]
R237  0  [r201-6p6spc]
R242  0  [r201-6p6spc]
R243  0  [r201-6p6spc]
R263  0  [r201-6p6spc]
R525  0  [r402-25]
R526  0  [r402-25]
R527  NP  [r402-25]
R538  0  [r402-25]
R541  NP  [r402-25]
R602  0  [r201-6p6spc]
R609  0  [r201-6p6spc]
R613  0  [r201-6p6spc]
R621  0  [r201-6p6spc]
R626  0  [r201-6p6spc]
R667  NP  [r201-6p6spc]
TP53  TestPoint1_0  [tp-30RD13]
TP56  TestPoint1_0  [tp-30RD13]
sheet SH05 - SoC MLB
C470  0.1uF  [c201-6p6spc]
J9  NO-POP(2.54mm)  [jump1x2-6040]
J10  NO-POP(2.54mm)  [jump1x2-6040]
J12  NO-POP(2.54mm)  [jump1x2-6040]
P8  QSH-020-01-L-D-DP-A  [qsh-020-dp-A]
R129  NO-POP  [r201-6p6spc]
R133  NO-POP  [r201-6p6spc]
R136  NO-POP  [r201-6p6spc]
R137  NO-POP  [r201-6p6spc]
R139  NO-POP  [r201-6p6spc]
R148  NO-POP  [r201-6p6spc]
R182  100  [r402-25]
R183  100  [r402-25]
R184  100  [r402-25]
R460  0  [r201-6p6spc]
R462  0  [r402-25]
sheet SH07 - SoC GPMC
R158  0  [r201-6p6spc]
R160  0  [r201-6p6spc]
R161  0  [r201-6p6spc]
R163  10K  [r201-6p6spc]
R164  0  [r201-6p6spc]
R165  0  [r201-6p6spc]
R166  0  [r201-6p6spc]
R167  0  [r201-6p6spc]
R168  0  [r201-6p6spc]
R169  0  [r201-6p6spc]
R170  0  [r201-6p6spc]
R171  0  [r201-6p6spc]
R172  0  [r201-6p6spc]
R484  0  [r201-6p6spc]
R485  0  [r201-6p6spc]
R486  0  [r201-6p6spc]
R487  0  [r201-6p6spc]
R488  0  [r201-6p6spc]
R489  0  [r201-6p6spc]
R490  0  [r201-6p6spc]
R491  0  [r201-6p6spc]
R492  0  [r201-6p6spc]
R493  0  [r201-6p6spc]
R494  0  [r201-6p6spc]
R495  0  [r201-6p6spc]
R496  0  [r201-6p6spc]
R497  0  [r201-6p6spc]
R498  0  [r201-6p6spc]
R501  0  [r201-6p6spc]
R502  0  [r201-6p6spc]
R503  0  [r201-6p6spc]
R504  0  [r201-6p6spc]
R505  0  [r201-6p6spc]
R507  0  [r201-6p6spc]
R540  0  [r201-6p6spc]
R735  0  [r402-25]
R736  NO-POP  [r402-25]
R737  0  [r402-25]
R738  NO-POP  [r402-25]
R739  0  [r402-25]
R740  NO-POP  [r402-25]
R741  0  [r402-25]
R742  NO-POP  [r402-25]
R743  0  [r402-25]
R744  NO-POP  [r402-25]
R745  0  [r402-25]
R746  NO-POP  [r402-25]
R747  0  [r402-25]
R748  NO-POP  [r402-25]
TP38  TestPoint1_0  [tp1-18rd8]
sheet SH08 - SoC DDR EMIF1 INTERFACE
C514  0.1uF  [c201-6p6spc]
R811  NP  [r402-25]
R812  1K 1%  [r402-25]
R813  1K 1%  [r402-25]
sheet SH10 - SoC HDMI
C538  0.001uF  [c201-6p6spc]
C539  0.1uF  [c201-6p6spc]
E9  NFM21PC474R1C3D  [emi-NFM21p]
sheet SH11 - SoC VOUT1 PORT LCD
R188  22  [r201-6p6spc]
R189  22  [r201-6p6spc]
R197  22  [r201-6p6spc]
R198  22  [r201-6p6spc]
R199  22  [r201-6p6spc]
R202  22  [r201-6p6spc]
R203  22  [r201-6p6spc]
R212  22  [r201-6p6spc]
R213  22  [r201-6p6spc]
R217  0  [r201-6p6spc]
R218  22  [r201-6p6spc]
R220  22  [r201-6p6spc]
R542  22  [r201-6p6spc]
R544  22  [r201-6p6spc]
R545  22  [r201-6p6spc]
R550  22  [r201-6p6spc]
R551  22  [r201-6p6spc]
R552  22  [r201-6p6spc]
R556  22  [r201-6p6spc]
R557  22  [r201-6p6spc]
R563  22  [r201-6p6spc]
R564  22  [r201-6p6spc]
R571  22  [r201-6p6spc]
R572  22  [r201-6p6spc]
R582  22  [r201-6p6spc]
R586  0  [r201-6p6spc]
R595  22  [r201-6p6spc]
R598  22  [r201-6p6spc]
TP50  TestPoint1_0  [tp1-18rd8]
sheet SH12 - SoC VIDEO PORTS IN
R173  0  [r201-6p6spc]
R174  0  [r201-6p6spc]
R175  0  [r201-6p6spc]
R176  0  [r201-6p6spc]
R543  0  [r201-6p6spc]
R546  0  [r201-6p6spc]
R547  0  [r201-6p6spc]
sheet SH14 - SoC JTAG
J17  MIPI-QSH-030  [qsh-030-01-f]
R627  22  [r402-25]
R634  22  [r402-25]
R635  22  [r402-25]
R653  22  [r402-25]
R698  4.7K  [r402-25]
R700  4.7K  [r402-25]
R703  4.7K  [r402-25]
R704  4.7K  [r402-25]
R758  100  [r402-25]
R759  4.7K  [r402-25]
R760  NO-POP  [r402-25]
R761  0  [r402-25]
R762  0  [r402-25]
R829  4.7K  [r402-25]
sheet SH17 - SoC IO POWER
U52  J6ECO_09Dec2013  [sktbga-zkk-6334-p760]  (sections -1,-10,-11,-12,-13,-14,-15,-16,-17,-18,-19,-2,-20,-21,-22,-23,-3,-4,-5,-6,-7,-8,-9)

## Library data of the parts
R177 R527 R541 R736 R738 R740 R742 R744 R746 R748 R760 = R: Part #: R0402-NOPOP
R158 R160 R161 R164-R176 R217 R221 R224 R225 R231 R236 R237 R242 R243 R263 R460 R484-R498 R501-R505 R507 R540 R543 R546 R547 R586 R602 R609 R613 R621 R626 = R: Part #: 103158-0001R
R462 R525 R526 R538 R735 R737 R739 R741 R743 R745 R747 R761 R762 = R: Part #: 101370-0001R
R129 R133 R136 R137 R139 R148 R667 = R: Part #: R0201-NOPOP
TP53 TP56 = TestPoint1_0: Part #: TP-30RD13-NO-POP
C470 C539 = CAP_NP: Part #: 103241-1100R
J9 J10 J12 = HEADER_2: Part #: NO-POP
P8 = QSH-020-01-L-D-DP-A: Part #: 103429-0020R
R182-R184 R758 = R: Part #: 101370-1001R
R163 = R: Part #: 103158-1003R
TP38 TP50 = TestPoint1_0: Part #: TP-18RD8-NO-POP
C514 = CAP: Part #: 103241-1100R
R811 = R: Part #: r0402-nopop
R812 R813 = R: Part #: 102145-1002R
C538 = CAP_NP: Part #: 103367-1102R
E9 = NFM_1: Part #: 102569-1470R
R188 R189 R197-R199 R202 R203 R212 R213 R218 R220 R542 R544 R545 R550-R552 R556 R557 R563 R564 R571 R572 R582 R595 R598 = R: Part #: 103158-2200R
J17 = MIPI-QTH-030_1: Part #: 101884-0030R
R627 R634 R635 R653 = R: Part #: 101370-2200R
R698 R700 R703 R704 R759 R829 = R: Part #: 101370-4702R
U52 = J6ECO_RevC_0: Part #: 104492-0002R-TI

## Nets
GND: C470.2 C514.2 C538.2 C539.2 E9.2 J17.16(Gnd16) J17.57(Gnd57) J17.58(Gnd58) J17.61(GndCt1) J17.62(GndCt2) J17.63(GndCt3) J17.64(GndCt4) P8.41(SH_GND.1) P8.42(SH_GND.2) P8.43(SH_GND.4) P8.44(SH_GND.3) R129.2 R133.2 R136.2 R137.2 R139.2 R148.2 R700.2 R762.1 R813.1 U52.AD19(VSSA_HDMI.2) U52.AE19(VSSA_HDMI.1) ; also on sheet 11 12 13 14 15 16 17 18 20 21 22 23 24 25 26 27 28 29 30 31 32 33 34 35 36 37 38 39 40 41 42 43 44 45 46 47 48 49 50 51 52 53 54 55 56 57 58 59 62 63 64 65 66 67 68 69 70 71
VDDA_1V8_PHY2: E9.3 ; also on sheet 58 64 71
VDDA_HDMI: C538.1 C539.1 E9.1 U52.Y17(VDDA_HDMI)
AIC3106_MCLK: R263.2 ; also on sheet 34
AQSPI1_CS[0]: R747.1 ; also on sheet 26
AQSPI1_D[0]: R741.1 ; also on sheet 26
AQSPI1_D[1]: R743.1 ; also on sheet 26
AQSPI1_D[2]: R739.1 ; also on sheet 26
AQSPI1_D[3]: R737.1 ; also on sheet 26
AQSPI1_RTCLK: R735.1 ; also on sheet 26
AQSPI1_SCLK: R745.1 ; also on sheet 26
C_CSI2_0_DX0: U52.AE1(csi2_0_dx0) ; also on sheet 40
C_CSI2_0_DX1: U52.AF1(csi2_0_dx1) ; also on sheet 40
C_CSI2_0_DX2: U52.AF2(csi2_0_dx2) ; also on sheet 40
C_CSI2_0_DX3: U52.AH4(csi2_0_dx3) ; also on sheet 40
C_CSI2_0_DX4: U52.AH3(csi2_0_dx4) ; also on sheet 40
C_CSI2_0_DY0: U52.AD2(csi2_0_dy0) ; also on sheet 40
C_CSI2_0_DY1: U52.AE2(csi2_0_dy1) ; also on sheet 40
C_CSI2_0_DY2: U52.AF3(csi2_0_dy2) ; also on sheet 40
C_CSI2_0_DY3: U52.AG4(csi2_0_dy3) ; also on sheet 40
C_CSI2_0_DY4: U52.AG3(csi2_0_dy4) ; also on sheet 40
C_CSI2_1_DX0: U52.AG5(csi2_1_dx0) ; also on sheet 40
C_CSI2_1_DX1: U52.AG6(csi2_1_dx1) ; also on sheet 40
C_CSI2_1_DX2: U52.AH7(csi2_1_dx2) ; also on sheet 40
C_CSI2_1_DY0: U52.AH5(csi2_1_dy0) ; also on sheet 40
C_CSI2_1_DY1: U52.AH6(csi2_1_dy1) ; also on sheet 40
C_CSI2_1_DY2: U52.AG7(csi2_1_dy2) ; also on sheet 40
C_GPMC_A0: R160.2 ; also on sheet 24 63
C_GPMC_A1: R507.2 ; also on sheet 63
C_GPMC_A2: R504.2 ; also on sheet 63
C_GPMC_A3: R505.2 ; also on sheet 63
C_GPMC_A4: R498.2 ; also on sheet 63
C_GPMC_A5: R503.2 ; also on sheet 63
C_GPMC_A6: R492.2 ; also on sheet 63
C_GPMC_A7: R491.2 ; also on sheet 63
C_GPMC_A8: R501.2 ; also on sheet 68
C_GPMC_A9: R493.2 ; also on sheet 68
C_GPMC_A10: R497.2 ; also on sheet 68
C_GPMC_A11: R502.2 ; also on sheet 68
C_GPMC_A12: U52.P4(GPMC_A12/qspi2_sclk/VIN2a_clk0/GPMC_a[0]/VIN1b_fld1/timer8/spi4_cs[1]/dma_evt1/gpio2_2) ; also on sheet 68
C_GPMC_A13: R736.1 ; also on sheet 70
C_GPMC_A14: R738.1 ; also on sheet 70
C_GPMC_A15: R740.1 ; also on sheet 70
C_GPMC_A16: R742.1 ; also on sheet 70
C_GPMC_A17: R744.1 ; also on sheet 70
C_GPMC_A18: R746.1 ; also on sheet 70
C_GPMC_A19: U52.K7(GPMC_A19/mmc2_dat[4]/GPMC_a[13]/VIN2a_d[12]/VIN2b_d[0]/gpio2_9) ; also on sheet 70
C_GPMC_A20: U52.M7(GPMC_A20/mmc2_dat[5]/GPMC_a[14]/VIN2a_d[13]/VIN2b_d[1]/gpio2_10) ; also on sheet 70
C_GPMC_A21: U52.J5(GPMC_A21/mmc2_dat[6]/GPMC_a[15]/VIN2a_d[14]/VIN2b_d[2]/gpio2_11) ; also on sheet 70
C_GPMC_A22: U52.K6(GPMC_A22/mmc2_dat[7]/GPMC_a[16]/VIN2a_d[15]/VIN2b_d[3]/gpio2_12) ; also on sheet 70
C_GPMC_A23: R495.2 ; also on sheet 70
C_GPMC_A24: U52.J4(GPMC_A24/mmc2_dat[0]/GPMC_a[18]/VIN2a_d[8]/VIN2b_d[5]/gpio2_14) ; also on sheet 70
C_GPMC_A25: U52.J6(GPMC_A25/mmc2_dat[1]/GPMC_a[19]/VIN2a_d[9]/VIN2b_d[6]/gpio2_15) ; also on sheet 70
C_GPMC_A26: U52.H4(GPMC_A26/mmc2_dat[2]/GPMC_a[20]/VIN2a_d[10]/VIN2b_d[7]/gpio2_16) ; also on sheet 70
C_GPMC_A27: U52.H5(GPMC_A27/mmc2_dat[3]/GPMC_a[21]/VIN2a_d[11]/VIN2b_hsync1/gpio2_17) ; also on sheet 70
C_GPMC_CLK: TP38.1 U52.P7(GPMC_CLK/GPMC_cs[7]/clkout1/GPMC_wait1/VIN2a_hsync0/VIN2a_de0/VIN2b_clk1/timer4/i2c3_scl/dma_evt1/gpio2_22/GPMC_a[20]) ; also on sheet 24
C_GPMC_D00: R488.1 ; also on sheet 63
C_GPMC_D01: R165.1 ; also on sheet 63
C_GPMC_D02: R487.1 ; also on sheet 63
C_GPMC_D03: R164.1 ; also on sheet 63
C_GPMC_D04: R496.1 ; also on sheet 63
C_GPMC_D05: R486.1 ; also on sheet 63
C_GPMC_D06: R485.1 ; also on sheet 63
C_GPMC_D07: R167.1 ; also on sheet 63
C_GPMC_D08: R166.1 ; also on sheet 63
C_GPMC_D09: R168.1 ; also on sheet 63
C_GPMC_D10: R169.1 ; also on sheet 63
C_GPMC_D11: R170.1 ; also on sheet 63
C_GPMC_D12: R171.1 ; also on sheet 63
C_GPMC_D13: R484.1 ; also on sheet 63
C_GPMC_D14: R172.1 ; also on sheet 63
C_GPMC_D15: R540.1 ; also on sheet 63
C_GPMC_nCS1: R494.2 ; also on sheet 70
C_GPMC_nCS2: R748.1 ; also on sheet 24 70
C_GPMC_nCS3: R161.2 ; also on sheet 24 68
C_MCA1_ACLKX: R602.1 ; also on sheet 66
C_MCA1_AFSX: R609.1 ; also on sheet 66
C_MCA1_AXR0: U52.G12(MCASP1_AXR00/uart6_rxd/VIN1a_vsync0/i2c5_sda/pr2_mii0_rxer/pr2_pru1_pru_r31[8]/pr2_pru1_pru_r30[8]/gpio5_2) ; also on sheet 66
C_MCA1_AXR1: U52.F12(MCASP1_AXR01/uart6_txd/VIN1a_hsync0/i2c5_scl/pr2_mii_mt0_clk/pr2_pru1_pru_r31[9]/pr2_pru1_pru_r30[9]/gpio5_3) ; also on sheet 66
C_MCA2_ACLKX: R242.1 ; also on sheet 66
C_MCA2_AFSX: R236.2 ; also on sheet 66
C_MCA2_AXR0: U52.B15(MCASP2_AXR0/VOUT2_d[10]/VIN2a_d[10]) ; also on sheet 66
C_MCA2_AXR1: U52.A15(MCASP2_AXR1/VOUT2_d[11]/VIN2a_d[11]) ; also on sheet 66
C_MCA2_AXR2: U52.C15(MCASP2_AXR2/MCASP3_axr[2]/VIN1a_d[5]/pr2_mii0_rxd0/pr2_pru0_pru_r31[16]/pr2_pru0_pru_r30[16]/gpio6_8) ; also on sheet 66
C_MCA2_AXR3: U52.A16(MCASP2_AXR3/MCASP3_axr[3]/VIN1a_d[4]/pr2_mii0_rxlink/pr2_pru0_pru_r31[17]/pr2_pru0_pru_r30[17]/gpio6_9) ; also on sheet 66
C_MCA2_AXR4: U52.D15(MCASP2_AXR4/MCASP8_axr[0]/VOUT2_d[12]/VIN2a_d[12]/gpio1_4) ; also on sheet 66
C_MCA2_AXR5: U52.B16(MCASP2_AXR5/MCASP8_axr[1]/VOUT2_d[13]/VIN2a_d[13]/gpio6_7) ; also on sheet 66
C_MCA2_AXR6: U52.B17(MCASP2_AXR6/MCASP8_aclkx/MCASP8_aclkr/VOUT2_d[14]/VIN2a_d[14]/gpio2_29) ; also on sheet 66
C_MCA2_AXR7: U52.A17(MCASP2_AXR7/MCASP8_fsx/MCASP8_fsr/VOUT2_d[15]/VIN2a_d[15]/gpio1_5) ; also on sheet 66
C_MCA3_ACLKX: R237.1 ; also on sheet 66
C_MCA3_AFSX: R224.2 ; also on sheet 66
C_MCA3_AXR0: R243.2 ; also on sheet 66
C_MCA3_AXR1: R621.2 ; also on sheet 66
C_MCA6_AXR0: U52.B12(MCASP1_AXR08/MCASP6_axr[0]/spi3_sclk/VIN1a_d[15]/timer5/pr2_mii0_txen/pr2_pru1_pru_r31[10]/pr2_pru1_pru_r30[10]/gpio5_10) ; also on sheet 66
C_MCA6_AXR1: U52.A11(MCASP1_AXR09/MCASP6_axr[1]/spi3_d[1]/VIN1a_d[14]/timer6/pr2_mii0_txd3/pr2_pru1_pru_r31[11]/pr2_pru1_pru_r30[11]/gpio5_11) ; also on sheet 66
C_MCA6_CLKX: R225.1 ; also on sheet 66
C_MCA6_FSX: R221.1 ; also on sheet 66
C_MCA7_AXR0: U52.E14(MCASP1_AXR12/MCASP7_axr[0]/spi3_cs[1]/VIN1a_d[11]/timer9/pr2_mii0_txd0/pr2_pru1_pru_r31[14]/pr2_pru1_pru_r30[14]/gpio4_18) ; also on sheet 66
C_MCA7_AXR1: U52.A13(MCASP1_AXR13/MCASP7_axr[1]/VIN1a_d[10]/timer10/pr2_mii_mr0_clk/pr2_pru1_pru_r31[15]/pr2_pru1_pru_r30[15]/gpio6_4) ; also on sheet 66
C_MCA7_CLKX: R613.1 ; also on sheet 66
C_MCA7_FSX: R231.1 ; also on sheet 66
C_VIN[2]A_CLK: R173.1 ; also on sheet 25
C_VIN[2]A_D[0]: U52.F2(VIN2A_D00/VOUT2_d[23]/emu10/uart9_ctsn/spi4_d[0]/kbd_row4/ehrpwm1B/pr1_uart0_rxd/pr1_edio_data_in5/pr1_edio_data_out5/gpio4_1) ; also on sheet 25
C_VIN[2]A_D[1]: U52.F3(VIN2A_D01/VOUT2_d[22]/emu11/uart9_rtsn/spi4_cs[0]/kbd_row5/ehrpwm1_tripzone_input/pr1_uart0_txd/pr1_edio_data_in6/pr1_edio_dat) ; also on sheet 25
C_VIN[2]A_D[2]: U52.D1(VIN2A_D02/VOUT2_d[21]/emu12/gmii1_crs/uart10_rxd/kbd_row6/eCAP1_in_PWM1_out/pr1_ecap0_ecap_capin_apwm_o/pr1_edio_data_in7/pr1_) ; also on sheet 25
C_VIN[2]A_D[3]: U52.E2(VIN2A_D03/VOUT2_d[20]/emu13/gmii1_rxer/uart10_txd/kbd_col0/ehrpwm1_synci/pr1_edc_latch0_in/pr1_pru1_pru_r31[0]/pr1_pru1_pru_r3) ; also on sheet 25
C_VIN[2]A_D[4]: U52.D2(VIN2A_D04/VOUT2_d[19]/emu14/gmii1_rxclk/uart10_ctsn/kbd_col1/ehrpwm1_synco/pr1_edc_sync0_out/pr1_pru1_pru_r31[1]/pr1_pru1_pru_) ; also on sheet 25
C_VIN[2]A_D[5]: U52.F4(VIN2A_D05/VOUT2_d[18]/emu15/gmii1_rxd[0]/uart10_rtsn/kbd_col2/eQEP2A_in/pr1_edio_sof/pr1_pru1_pru_r31[2]/pr1_pru1_pru_r30[2]/g) ; also on sheet 25
C_VIN[2]A_D[6]: U52.C1(VIN2A_D06/VOUT2_d[17]/emu16/gmii1_rxd[1]/mii1_rxd[1]/kbd_col3/eQEP2B_in/pr1_mii_mt1_clk/pr1_pru1_pru_r31[3]/pr1_pru1_pru_r30[3) ; also on sheet 25
C_VIN[2]A_D[7]: U52.E4(VIN2A_D07/VOUT2_d[16]/emu17/gmii1_rxd[2]/mii1_rxd[2]/kbd_col4/eQEP2_index/pr1_mii1_txen/pr1_pru1_pru_r31[4]/pr1_pru1_pru_r30[4) ; also on sheet 25
C_VIN[2]A_D[8]: U52.F5(VIN2A_D08/VOUT2_d[15]/emu18/gmii1_rxd[3]/mii1_rxd[3]/kbd_col5/eQEP2_strobe/pr1_mii1_txd3/pr1_pru1_pru_r31[5]/pr1_pru1_pru_r30[) ; also on sheet 25
C_VIN[2]A_D[9]: U52.E6(VIN2A_D09/VOUT2_d[14]/emu19/gmii1_rxd[4]/mii1_rxd[0]/kbd_col6/ehrpwm2A/pr1_mii1_txd2/pr1_pru1_pru_r31[6]/pr1_pru1_pru_r30[6]/g) ; also on sheet 25
C_VIN[2]A_D[10]: U52.D3(VIN2A_D10/mdio_mclk/VOUT2_d[13]/gmii1_rxd[5]/kbd_col7/ehrpwm2B/pr1_mdio_mdclk/pr1_pru1_pru_r31[7]/pr1_pru1_pru_r30[7]/gpio4_11) ; also on sheet 25
C_VIN[2]A_D[11]: U52.F6(VIN2A_D11/mdio_d/VOUT2_d[12]/gmii1_rxd[6]/kbd_row7/ehrpwm2_tripzone_input/pr1_mdio_data/pr1_pru1_pru_r31[8]/pr1_pru1_pru_r30[8) ; also on sheet 25
C_VIN[2]A_D[12]: R547.1 ; also on sheet 25
C_VIN[2]A_D[13]: R174.1 ; also on sheet 25
C_VIN[2]A_D[14]: R176.1 ; also on sheet 25
C_VIN[2]A_D[15]: R543.1 ; also on sheet 25
C_VIN[2]A_D[16]: R175.1 ; also on sheet 25
C_VIN[2]A_D[17]: R546.1 ; also on sheet 25
C_VIN[2]A_D[18]: U52.C5(VIN2A_D18/VIN2b_d[5]/RGMII1_rxc/VOUT2_d[5]/gmii1_txd[3]/mii1_txd[3]/ehrpwm3B/pr1_mii1_rxd1/pr1_pru1_pru_r31[15]/pr1_pru1_pru_r) ; also on sheet 25
C_VIN[2]A_D[19]: U52.A3(VIN2A_D19/VIN2b_d[4]/RGMII1_rxctl/VOUT2_d[4]/gmii1_txd[4]/mii1_txer/ehrpwm3_tripzone_input/pr1_mii1_rxd0/pr1_pru1_pru_r31[16]/) ; also on sheet 25
C_VIN[2]A_D[20]: U52.B3(VIN2A_D20/VIN2b_d[3]/RGMII1_rxd[3]/VOUT2_d[3]/gmii1_txd[5]/mii1_rxer/eCAP3_in_PWM3_out/pr1_mii1_rxer/pr1_pru1_pru_r31[17]/pr1_) ; also on sheet 25
C_VIN[2]A_D[21]: U52.B4(VIN2A_D21/VIN2b_d[2]/RGMII1_rxd[2]/VOUT2_d[2]/gmii1_txd[6]/mii1_col/pr1_mii1_rxlink/pr1_pru1_pru_r31[18]/pr1_pru1_pru_r30[18]/) ; also on sheet 25
C_VIN[2]A_D[22]: U52.B5(VIN2A_D22/VIN2b_d[1]/RGMII1_rxd[1]/VOUT2_d[1]/gmii1_txd[7]/mii1_crs/pr1_mii1_col/pr1_pru1_pru_r31[19]/pr1_pru1_pru_r30[19]/gpi) ; also on sheet 25
C_VIN[2]A_D[23]: U52.A4(VIN2A_D23/VIN2b_d[0]/RGMII1_rxd[0]/VOUT2_d[0]/gmii1_txen/mii1_txen/pr1_mii1_crs/pr1_pru1_pru_r31[20]/pr1_pru1_pru_r30[20]/gpio) ; also on sheet 25
C_VIN[2]A_DE0: U52.G2(VIN2A_DE0/VIN2a_fld0/VIN2b_fld1/VIN2b_de1/VOUT2_de/emu6/gmii1_txclk/kbd_row1/eQEP1B_in/pr1_edio_data_in1/pr1_edio_data_out1/gp) ; also on sheet 25
C_VIN[2]A_FLD0: U52.H7(VIN2A_FLD0/VIN2b_clk1/VOUT2_clk/emu7/gmii1_col/eQEP1_index/pr1_edio_data_in2/pr1_edio_data_out2/gpio3_30/GPMC_a[27]__gpmc_a[18) ; also on sheet 25
C_VIN[2]A_HSYNC0: U52.G1(VIN2A_HSYNC0/VIN2b_hsync1/VOUT2_hsync/emu8/uart9_rxd/spi4_sclk/kbd_row2/eQEP1_strobe/pr1_uart0_cts_n/pr1_edio_data_in3/pr1_edi) ; also on sheet 25
C_VIN[2]A_VSYNC0: U52.G6(VIN2A_VSYNC0/VIN2b_vsync1/VOUT2_vsync/emu9/uart9_txd/spi4_d[1]/kbd_row3/ehrpwm1A/pr1_uart0_rts_n/pr1_edio_data_in4/pr1_edio_da) ; also on sheet 25
C_XREF_CLK1: R626.2 ; also on sheet 66
CPU_HDMI_TX0+: U52.AH17(HDMI1_DATA0Y) ; also on sheet 38
CPU_HDMI_TX0-: U52.AG17(HDMI1_DATA0X) ; also on sheet 38
CPU_HDMI_TX1+: U52.AH18(HDMI1_DATA1Y) ; also on sheet 38
CPU_HDMI_TX1-: U52.AG18(HDMI1_DATA1X) ; also on sheet 38
CPU_HDMI_TX2+: U52.AH19(HDMI1_DATA2Y) ; also on sheet 38
CPU_HDMI_TX2-: U52.AG19(HDMI1_DATA2X) ; also on sheet 38
CPU_HDMI_TXC+: U52.AH16(HDMI1_CLOCKY) ; also on sheet 38
CPU_HDMI_TXC-: U52.AG16(HDMI1_CLOCKX) ; also on sheet 38
CPU_VDD_DDR: R812.1 ; also on sheet 15 55
DDR1_A0: U52.AD20(DDR1_A0) ; also on sheet 19 20 21 23
DDR1_A1: U52.AC19(DDR1_A1) ; also on sheet 19 20 21 23
DDR1_A2: U52.AC20(DDR1_A2) ; also on sheet 19 20 21 23
DDR1_A3: U52.AB19(DDR1_A3) ; also on sheet 19 20 21 23
DDR1_A4: U52.AF21(DDR1_A4) ; also on sheet 19 20 21 23
DDR1_A5: U52.AH22(DDR1_A5) ; also on sheet 19 20 21 23
DDR1_A6: U52.AG23(DDR1_A6) ; also on sheet 19 20 21 23
DDR1_A7: U52.AE21(DDR1_A7) ; also on sheet 19 20 21 23
DDR1_A8: U52.AF22(DDR1_A8) ; also on sheet 19 20 21 23
DDR1_A9: U52.AE22(DDR1_A9) ; also on sheet 19 20 21 23
DDR1_A10: U52.AD21(DDR1_A10) ; also on sheet 19 20 21 23
DDR1_A11: U52.AD22(DDR1_A11) ; also on sheet 19 20 21 23
DDR1_A12: U52.AC21(DDR1_A12) ; also on sheet 19 20 21 23
DDR1_A13: U52.AF18(DDR1_A13) ; also on sheet 19 20 21 23
DDR1_A14: U52.AE17(DDR1_A14) ; also on sheet 19 20 21 23
DDR1_A15: U52.AD18(DDR1_A15) ; also on sheet 19 20 21 23
DDR1_BA0: U52.AF17(DDR1_BA0) ; also on sheet 19 20 21 23
DDR1_BA1: U52.AE18(DDR1_BA1) ; also on sheet 19 20 21 23
DDR1_BA2: U52.AB18(DDR1_BA2) ; also on sheet 19 20 21 23
DDR1_CASN: U52.AC18(DDR1_CASN) ; also on sheet 19 20 21 23
DDR1_CKE: U52.AG22(DDR1_CKE) ; also on sheet 19 20 21 23
DDR1_CLK0: U52.AG24(DDR1_CK) ; also on sheet 19 20 21 23
DDR1_CLK0N: U52.AH24(DDR1_NCK) ; also on sheet 19 20 21 23
DDR1_CSN0: U52.AH23(DDR1_CS0N) ; also on sheet 19 20 21 23
DDR1_CSN1: U52.AB16(DDR1_CS1N) ; also on sheet 19 20 21 23
DDR1_D0: U52.AF25(DDR1_D0) ; also on sheet 21
DDR1_D1: U52.AF26(DDR1_D1) ; also on sheet 21
DDR1_D2: U52.AG26(DDR1_D2) ; also on sheet 21
DDR1_D3: U52.AH26(DDR1_D3) ; also on sheet 21
DDR1_D4: U52.AF24(DDR1_D4) ; also on sheet 21
DDR1_D5: U52.AE24(DDR1_D5) ; also on sheet 21
DDR1_D6: U52.AF23(DDR1_D6) ; also on sheet 21
DDR1_D7: U52.AE23(DDR1_D7) ; also on sheet 21
DDR1_D8: U52.AC23(DDR1_D8) ; also on sheet 21
DDR1_D9: U52.AF27(DDR1_D9) ; also on sheet 21
DDR1_D10: U52.AG27(DDR1_D10) ; also on sheet 21
DDR1_D11: U52.AF28(DDR1_D11) ; also on sheet 21
DDR1_D12: U52.AE26(DDR1_D12) ; also on sheet 21
DDR1_D13: U52.AC25(DDR1_D13) ; also on sheet 21
DDR1_D14: U52.AC24(DDR1_D14) ; also on sheet 21
DDR1_D15: U52.AD25(DDR1_D15) ; also on sheet 21
DDR1_D16: U52.V20(DDR1_D16) ; also on sheet 21
DDR1_D17: U52.W20(DDR1_D17) ; also on sheet 21
DDR1_D18: U52.AB28(DDR1_D18) ; also on sheet 21
DDR1_D19: U52.AC28(DDR1_D19) ; also on sheet 21
DDR1_D20: U52.AC27(DDR1_D20) ; also on sheet 21
DDR1_D21: U52.Y19(DDR1_D21) ; also on sheet 21
DDR1_D22: U52.AB27(DDR1_D22) ; also on sheet 21
DDR1_D23: U52.Y20(DDR1_D23) ; also on sheet 21
DDR1_D24: U52.AA23(DDR1_D24) ; also on sheet 21
DDR1_D25: U52.Y22(DDR1_D25) ; also on sheet 21
DDR1_D26: U52.Y23(DDR1_D26) ; also on sheet 21
DDR1_D27: U52.AA24(DDR1_D27) ; also on sheet 21
DDR1_D28: U52.Y24(DDR1_D28) ; also on sheet 21
DDR1_D29: U52.AA26(DDR1_D29) ; also on sheet 21
DDR1_D30: U52.AA25(DDR1_D30) ; also on sheet 21
DDR1_D31: U52.AA28(DDR1_D31) ; also on sheet 21
DDR1_DQM0: U52.AD23(DDR1_DQM0) ; also on sheet 21
DDR1_DQM1: U52.AB23(DDR1_DQM1) ; also on sheet 21
DDR1_DQM2: U52.AC26(DDR1_DQM2) ; also on sheet 21
DDR1_DQM3: U52.AA27(DDR1_DQM3) ; also on sheet 21
DDR1_DQM_ECC: U52.V26(DDR1_DQM_ECC) ; also on sheet 20
DDR1_DQS0: U52.AH25(DDR1_DQS0) ; also on sheet 21
DDR1_DQS1: U52.AE27(DDR1_DQS1) ; also on sheet 21
DDR1_DQS2: U52.AD27(DDR1_DQS2) ; also on sheet 21
DDR1_DQS3: U52.Y28(DDR1_DQS3) ; also on sheet 21
DDR1_DQS_ECC: U52.V27(DDR1_DQS_ECC) ; also on sheet 20
DDR1_DQSN0: U52.AG25(DDR1_DQSN0) ; also on sheet 21
DDR1_DQSN1: U52.AE28(DDR1_DQSN1) ; also on sheet 21
DDR1_DQSN2: U52.AD28(DDR1_DQSN2) ; also on sheet 21
DDR1_DQSN3: U52.Y27(DDR1_DQSN3) ; also on sheet 21
DDR1_DQSN_ECC: U52.V28(DDR1_DQSN_ECC) ; also on sheet 20
DDR1_ECC_D0: U52.W22(DDR1_ECC_D0) ; also on sheet 20
DDR1_ECC_D1: U52.V23(DDR1_ECC_D1) ; also on sheet 20
DDR1_ECC_D2: U52.W19(DDR1_ECC_D2) ; also on sheet 20
DDR1_ECC_D3: U52.W23(DDR1_ECC_D3) ; also on sheet 20
DDR1_ECC_D4: U52.Y25(DDR1_ECC_D4) ; also on sheet 20
DDR1_ECC_D5: U52.V24(DDR1_ECC_D5) ; also on sheet 20
DDR1_ECC_D6: U52.V25(DDR1_ECC_D6) ; also on sheet 20
DDR1_ECC_D7: U52.Y26(DDR1_ECC_D7) ; also on sheet 20
DDR1_ODT0: U52.AE20(DDR1_ODT0) ; also on sheet 19 20 21 23
DDR1_ODT1: U52.AC17(DDR1_ODT1) ; also on sheet 19 20 21 23
DDR1_RASN: U52.AF20(DDR1_RASN) ; also on sheet 19 20 21 23
DDR1_WEN: U52.AH21(DDR1_WEN) ; also on sheet 19 20 21 23
DDR_VREFSTL1: R811.1 ; also on sheet 20 21 55
EMU0: J17.19(TRD0.1) R627.1 R704.2
EMU1: J17.21(TRD0.2) R653.1 R698.2
EMU_RSTn: J17.6(nRESET) R703.2 ; also on sheet 11
EVM_3V3: P8.37 P8.38 P8.39 R163.1 R698.1 R703.1 R704.1 R758.1 R759.1 R829.1 ; also on sheet 11 24 25 26 27 28 29 30 31 32 33 34 35 36 37 38 39 40 42 43 44 45 46 47 48 49 50 51 55 56 58 59 62 63 65 66 67 69 70
EVM_12V: P8.40 ; also on sheet 36 50 53 54 58
GP2[27]: U52.M4(GPMC_BEN1/GPMC_cs[5]/VIN2b_clk1/GPMC_a[3]/VIN2b_fld1/timer1/dma_evt4/gpio2_27/GPMC_a[22]) ; also on sheet 24 50
GP5[0]: U52.B14(MCASP1_ACLKR/MCASP7_axr[2]/VOUT2_d[0]/VIN2a_d[0]/i2c4_sda/gpio5_0) ; also on sheet 50 59
GP5[1]: U52.J14(MCASP1_FSR/MCASP7_axr[3]/VOUT2_d[1]/VIN2a_d[1]/i2c4_scl/gpio5_1) ; also on sheet 50
GP5[4]: U52.G13(MCASP1_AXR02/MCASP6_axr[2]/uart6_ctsn/VOUT2_d[2]/VIN2a_d[2]/gpio5_4) ; also on sheet 44
GP5[5]: U52.J11(MCASP1_AXR03/MCASP6_axr[3]/uart6_rtsn/VOUT2_d[3]/VIN2a_d[3]/gpio5_5) ; also on sheet 44
GP5[6]: U52.E12(MCASP1_AXR04/MCASP4_axr[2]/VOUT2_d[4]/VIN2a_d[4]/gpio5_6) ; also on sheet 44
GP5[7]: U52.F13(MCASP1_AXR05/MCASP4_axr[3]/VOUT2_d[5]/VIN2a_d[5]/gpio5_7) ; also on sheet 44
GP5[8]: U52.C12(MCASP1_AXR06/MCASP5_axr[2]/VOUT2_d[6]/VIN2a_d[6]/gpio5_8) ; also on sheet 44
GP5[9]: P8.34 U52.D12(MCASP1_AXR07/MCASP5_axr[3]/VOUT2_d[7]/VIN2a_d[7]/timer4/gpio5_9)
GP6[17]: U52.D18(XREF_CLK0/MCASP2_axr[8]/MCASP1_axr[4]/MCASP1_ahclkx/MCASP5_ahclkx/atl_clk0/VIN1a_d[0]/hdq0/clkout2/timer13/pr2_mii1_col/pr2_pr) ; also on sheet 49
GP6[20]: U52.C23(XREF_CLK3/MCASP2_axr[11]/MCASP1_axr[7]/MCASP4_ahclkx/MCASP8_ahclkx/atl_clk3/VOUT2_de/hdq0/VIN2a_de0/clkout3/timer16/gpio6_20) ; also on sheet 51
GP6_[28]: P8.24 ; also on sheet 61
GPMC_ADVn_ALE: U52.N1(GPMC_ADVN_ALE/GPMC_cs[6]/clkout2/GPMC_wait1/VIN2a_vsync0/GPMC_a[2]/GPMC_a[23]/timer3/i2c3_sda/dma_evt2/gpio2_23/GPMC_a[19]) ; also on sheet 24
GPMC_BE0n_CLE: U52.N6(GPMC_BEN0/GPMC_cs[4]/VIN2b_de1/timer2/dma_evt3/gpio2_26/GPMC_a[21]) ; also on sheet 24
GPMC_nCS0: R158.2 ; also on sheet 27 28
GPMC_OEN_REN: R489.2 ; also on sheet 27 28
GPMC_WAIT: R163.2 U52.N2(GPMC_WAIT0/gpio2_28/GPMC_a[25]__gpmc_a[15]) ; also on sheet 24
GPMC_WEn: R490.2 ; also on sheet 27 28
I2C1_SCL: P8.33 ; also on sheet 34 37 42 45 50 56 62 69
I2C1_SDA: P8.35 ; also on sheet 34 37 42 45 50 56 62 69
I2C4_SCL: U52.A21(MCASP4_FSX/MCASP4_fsr/spi3_d[1]/uart8_txd/i2c4_scl/VOUT2_d[17]/VIN2a_d[17]/VIN1a_d[14]) ; also on sheet 49
I2C4_SDA: U52.C18(MCASP4_ACLKX/MCASP4_aclkr/spi3_sclk/uart8_rxd/i2c4_sda/VOUT2_d[16]/VIN2a_d[16]/VIN1a_d[15]) ; also on sheet 49
J6_VDD_1V8: C470.1 U52.AA7(VDDS_MLBP.1) U52.Y7(VDDS_MLBP.2) ; also on sheet 11 13 14 56 57 59
J6E_DDR1_RST: U52.AG21(DDR1_RST) ; also on sheet 23
LCD_B0: R598.1 ; also on sheet 37
LCD_B1: R213.1 ; also on sheet 37
LCD_B2: J17.13(TR_CLK0) R217.1 ; also on sheet 37
LCD_B3: J17.25(TRD0.4) R218.1 ; also on sheet 37
LCD_B4: J17.27(TRD0.5) R572.1 ; also on sheet 37
LCD_B5: J17.29(TRD0.6) R556.1 ; also on sheet 37
LCD_B6: J17.31(TRD0.7) R564.1 ; also on sheet 37
LCD_B7: J17.33(TRD0.8) R542.1 ; also on sheet 37
LCD_DE: R212.1 ; also on sheet 37
LCD_G0: R544.1 ; also on sheet 37
LCD_G1: R563.1 ; also on sheet 37
LCD_G2: J17.17(TRD0.0) R551.1 ; also on sheet 37
LCD_G3: J17.35(TRD0.9) R545.1 ; also on sheet 37
LCD_G4: J17.37(TRD3.0) R188.1 ; also on sheet 37
LCD_G5: J17.39(TRD3.1) R552.1 ; also on sheet 37
LCD_G6: J17.41(TRD3.2) R550.1 ; also on sheet 37
LCD_G7: J17.43(TRD3.3) R557.1 ; also on sheet 37
LCD_HS: R582.1 ; also on sheet 37
LCD_PCLK: R586.1 ; also on sheet 37
LCD_R0: R189.1 ; also on sheet 37
LCD_R1: R199.1 ; also on sheet 37
LCD_R2: J17.23(TRD0.3) R197.1 ; also on sheet 37
LCD_R3: J17.45(TRD3.4) R198.1 ; also on sheet 37
LCD_R4: J17.47(TRD3.5) R571.1 ; also on sheet 37
LCD_R5: J17.49(TRD3.6) R203.1 ; also on sheet 37
LCD_R6: J17.51(TRD3.7) R202.1 ; also on sheet 37
LCD_R7: J17.53(TRD3.8) R220.1 ; also on sheet 37
LCD_VS: R595.1 ; also on sheet 37
MCA4_AXR0: U52.G16(MCASP4_AXR0/spi3_d[0]/uart8_ctsn/uart4_rxd/VOUT2_d[18]/VIN2a_d[18]/VIN1a_d[13]/i2c6_scl) ; also on sheet 49
MCA4_AXR1: U52.D17(MCASP4_AXR1/spi3_cs[0]/uart8_rtsn/uart4_txd/VOUT2_d[19]/VIN2a_d[19]/VIN1a_d[12]/pr2_pru1_pru_r31[0]/pr2_pru1_pru_r30[0]/i2c6_s) ; also on sheet 49
MCA5_ACLKX: R538.2 ; also on sheet 49
MCA5_AXR0: R526.2 ; also on sheet 49
MCA5_AXR1: R525.2 ; also on sheet 49
MCA5_FSX: U52.AB9(MCASP5_FSX/MCASP5_fsr/spi4_d[1]/uart9_txd/i2c5_scl/VOUT2_d[21]/VIN2a_d[21]/VIN1a_d[10]/pr2_pru1_pru_r31[2]/pr2_pru1_pru_r30[2]) ; also on sheet 49
MLBP_CLK: P8.2 R541.2
MLBP_CLK_N: J9.1 P8.17 R133.1 R184.2 U52.AB2(MLBP_CLK_N)
MLBP_CLK_P: J9.2 P8.19 R129.1 R184.1 U52.AB1(MLBP_CLK_P)
MLBP_DAT: P8.10 R177.2
MLBP_DAT_N: J10.1 P8.9 R137.1 R183.2 U52.AA2(MLBP_DAT_N)
MLBP_DAT_P: J10.2 P8.11 R136.1 R183.1 U52.AA1(MLBP_DAT_P)
MLBP_SIG: P8.6 R527.2
MLBP_SIG_N: J12.1 P8.1 R148.1 R182.2 U52.AC2(MLBP_SIG_N)
MLBP_SIG_P: J12.2 P8.3 R139.1 R182.1 U52.AC1(MLBP_SIG_P)
nTRST: J17.9(nTRST) R759.2 R760.1
RC_GPMC_A13: R735.2 R736.2 U52.R3(GPMC_A13/qspi1_rtclk/VIN2a_hsync0/timer7/spi4_cs[2]/dma_evt2/gpio2_3)
RC_GPMC_A14: R737.2 R738.2 U52.T2(GPMC_A14/qspi1_d[3]/VIN2a_vsync0/timer6/spi4_cs[3]/gpio2_4)
RC_GPMC_A15: R739.2 R740.2 U52.U2(GPMC_A15/qspi1_d[2]/VIN2a_d[8]/timer5/gpio2_5)
RC_GPMC_A16: R741.2 R742.2 U52.U1(GPMC_A16/qspi1_d[1]/VIN2a_d[9]/gpio2_6)
RC_GPMC_A17: R743.2 R744.2 U52.P3(GPMC_A17/qspi1_d[0]/VIN2a_d[10]/gpio2_7)
RC_GPMC_A18: R745.2 R746.2 U52.R2(GPMC_A18/qspi1_sclk/VIN2a_d[11]/gpio2_8)
RC_GPMC_nCS2: R747.2 R748.2 U52.P2(GPMC_CS2/qspi1_cs[0]/gpio2_20/GPMC_a[23]__gpmc_a[13])
RSTOUTn: R460.1 ; also on sheet 11 26 28 29 34 35 40 56 59
RTCK: J17.7(RTCK) R635.1
TCK: J17.3(TCK) U52.E20(TCLK)
TDI: J17.5(TDI) U52.D23(TDI)
TDO: J17.4(TDO) R634.1
TMS: J17.2(TMS) R829.2 U52.F18(TMS)
TRSTn: R760.2 R761.2 U52.D20(TRSTN)
TRSTPD: J17.8(TRSTPD) R700.1 R761.1
XREF_CLK2: R462.2 R667.2
N17148400: C514.1 R811.2 R812.2 R813.2 U52.Y18(DDR1_VREF0)
N18657599: R635.2 U52.E18(RTCK)
N18658959: R634.2 U52.F19(TDO)
N19059235: J17.1(VREF_DBG) J17.12(VREF_TR) R758.2
N19060121: J17.15(TGT_DETECT) R762.2
N19152868: P8.16 R462.1
N19152900: P8.25 R460.2
N23554459: R165.2 U52.M2(GPMC_AD01/VIN1a_d[1]/VOUT3_d[1]/gpio1_7/sysboot1)
N23554461: R164.2 U52.M1(GPMC_AD03/VIN1a_d[3]/VOUT3_d[3]/gpio1_9/sysboot3)
N23554463: R540.2 U52.H3(GPMC_AD15/VIN1a_d[15]/VOUT3_d[15]/gpio1_21/sysboot15)
N23554465: R172.2 U52.H2(GPMC_AD14/VIN1a_d[14]/VOUT3_d[14]/gpio1_20/sysboot14)
N23554467: R484.2 U52.J3(GPMC_AD13/VIN1a_d[13]/VOUT3_d[13]/gpio1_19/sysboot13)
N23554469: R171.2 U52.H1(GPMC_AD12/VIN1a_d[12]/VOUT3_d[12]/gpio1_18/sysboot12)
N23554471: R170.2 U52.J2(GPMC_AD11/VIN1a_d[11]/VOUT3_d[11]/gpio7_29/sysboot11)
N23554473: R169.2 U52.J1(GPMC_AD10/VIN1a_d[10]/VOUT3_d[10]/gpio7_28/sysboot10)
N23554475: R168.2 U52.K2(GPMC_AD09/VIN1a_d[9]/VOUT3_d[9]/gpio7_19/sysboot9)
N23554477: R166.2 U52.L1(GPMC_AD08/VIN1a_d[8]/VOUT3_d[8]/gpio7_18/sysboot8)
N23554479: R167.2 U52.L2(GPMC_AD07/VIN1a_d[7]/VOUT3_d[7]/gpio1_13/sysboot7)
N23554481: R487.2 U52.L5(GPMC_AD02/VIN1a_d[2]/VOUT3_d[2]/gpio1_8/sysboot2)
N23554483: R496.2 U52.L6(GPMC_AD04/VIN1a_d[4]/VOUT3_d[4]/gpio1_10/sysboot4)
N23554485: R486.2 U52.L4(GPMC_AD05/VIN1a_d[5]/VOUT3_d[5]/gpio1_11/sysboot5)
N23554487: R485.2 U52.L3(GPMC_AD06/VIN1a_d[6]/VOUT3_d[6]/gpio1_12/sysboot6)
N23554489: R488.2 U52.M6(GPMC_AD00/VIN1a_d[0]/VOUT3_d[0]/gpio1_6/sysboot0)
N23574443: TP53.1 U52.E15(MCASP2_ACLKR/MCASP8_axr[2]/VOUT2_d[8]/VIN2a_d[8])
N23574445: R538.1 R541.1 U52.AA3(MCASP5_ACLKX/MCASP5_aclkr/spi4_sclk/uart9_rxd/i2c5_sda/mlb_clk)
N23574451: R177.1 R525.1 U52.AA4(MCASP5_AXR1/spi4_cs[0]/uart9_rtsn/uart3_txd/mlb_dat)
N23574476: TP56.1 U52.A20(MCASP2_FSR/MCASP8_axr[3]/VOUT2_d[9]/VIN2a_d[9])
N23574496: R221.2 U52.A12(MCASP1_AXR11/MCASP6_fsx/MCASP6_fsr/spi3_cs[0]/VIN1a_d[12]/timer8/pr2_mii0_txd1/pr2_pru1_pru_r31[13]/pr2_pru1_pru_r30[13]/gpio4)
N23574498: R225.2 U52.B13(MCASP1_AXR10/MCASP6_aclkx/MCASP6_aclkr/spi3_d[0]/VIN1a_d[13]/timer7/pr2_mii0_txd2/pr2_pru1_pru_r31[12]/pr2_pru1_pru_r30[12]/gp)
N23574506: R242.2 U52.A19(MCASP2_ACLKX/VIN1a_d[7]/pr2_mii0_rxd2/pr2_pru0_pru_r31[18]/pr2_pru0_pru_r30[18])
N23574512: R231.2 U52.F14(MCASP1_AXR15/MCASP7_fsx/MCASP7_fsr/VIN1a_d[8]/timer12/pr2_mii0_rxd3/pr2_pru0_pru_r31[20]/pr2_pru0_pru_r30[20]/gpio6_6)
N23574514: R613.2 U52.G14(MCASP1_AXR14/MCASP7_aclkx/MCASP7_aclkr/VIN1a_d[9]/timer11/pr2_mii0_rxdv/pr2_pru1_pru_r31[16]/pr2_pru1_pru_r30[16]/gpio6_5)
N23574520: R237.2 U52.B18(MCASP3_ACLKX/MCASP3_aclkr/MCASP2_axr[12]/uart7_rxd/VIN1a_d[3]/pr2_mii0_crs/pr2_pru0_pru_r31[12]/pr2_pru0_pru_r30[12]/gpio5_13)
N23574522: R224.1 U52.F15(MCASP3_FSX/MCASP3_fsr/MCASP2_axr[13]/uart7_txd/VIN1a_d[2]/pr2_mii0_col/pr2_pru0_pru_r31[13]/pr2_pru0_pru_r30[13]/gpio5_14)
N23574524: R243.1 U52.B19(MCASP3_AXR0/MCASP2_axr[14]/uart7_ctsn/uart5_rxd/VIN1a_d[1]/pr2_mii1_rxer/pr2_pru0_pru_r31[14]/pr2_pru0_pru_r30[14])
N23574526: R621.1 U52.C17(MCASP3_AXR1/MCASP2_axr[15]/uart7_rtsn/uart5_txd/VIN1a_d[0]/VIN1a_fld0/pr2_mii1_rxlink/pr2_pru0_pru_r31[15]/pr2_pru0_pru_r30[15)
N23574528: R526.1 R527.1 U52.AB3(MCASP5_AXR0/spi4_d[0]/uart9_ctsn/uart3_rxd/mlb_sig)
N23574548: R602.2 U52.C14(MCASP1_ACLKX/VIN1a_fld0/i2c3_sda/pr2_mdio_mdclk/pr2_pru1_pru_r31[7]/pr2_pru1_pru_r30[7]/gpio7_31)
N23574558: R609.2 U52.D14(MCASP1_FSX/VIN1a_de0/i2c3_scl/pr2_mdio_data/gpio7_30)
N23574810: R236.1 U52.A18(MCASP2_FSX/VIN1a_d[6]/pr2_mii0_rxd1/pr2_pru0_pru_r31[19]/pr2_pru0_pru_r30[19])
N23574943: R263.1 R667.1 U52.B26(XREF_CLK2/MCASP2_axr[10]/MCASP1_axr[6]/MCASP3_ahclkx/MCASP7_ahclkx/atl_clk2/VOUT2_clk/VIN2a_clk0/timer15/gpio6_19)
N23574969: R626.1 U52.E17(XREF_CLK1/MCASP2_axr[9]/MCASP1_axr[5]/MCASP2_ahclkx/MCASP6_ahclkx/atl_clk1/VIN1a_clk0/timer14/pr2_mii1_crs/pr2_pru1_pru_r31[6])
N23577782: R158.1 U52.T1(GPMC_CS0/qspi2_cs[1]/gpio2_19)
N23577922: R494.1 U52.H6(GPMC_CS1/mmc2_cmd/GPMC_a[22]/VIN2a_de0/VIN2b_vsync1/gpio2_18)
N23578101: R498.1 U52.P6(GPMC_A04/qspi1_cs[3]/VIN1a_d[20]/VOUT3_d[20]/VIN2a_d[4]/usb4_ulpi_d3/VIN1b_d[4]/i2c5_scl/uart6_rxd/gpio1_26)
N23578103: R492.1 U52.R5(GPMC_A06/qspi2_cs[3]/VIN1a_d[22]/VOUT3_d[22]/VIN2a_d[6]/usb4_ulpi_d1/VIN1b_d[6]/uart8_rxd/uart6_ctsn/gpio1_28)
N23578115: R491.1 U52.P5(GPMC_A07/qspi2_rtclk/VIN1a_d[23]/VOUT3_d[23]/VIN2a_d[7]/usb4_ulpi_d0/VIN1b_d[7]/uart8_txd/uart6_rtsn/gpio1_29)
N23578117: R503.1 U52.R9(GPMC_A05/qspi2_cs[2]/VIN1a_d[21]/VOUT3_d[21]/VIN2a_d[5]/usb4_ulpi_d2/VIN1b_d[5]/i2c5_sda/uart6_txd/gpio1_27)
N23578143: R490.1 U52.M3(GPMC_WEN/gpio2_25)
N23578145: R489.1 U52.M5(GPMC_OEN_REN/gpio2_24)
N23578156: R161.1 U52.P1(GPMC_CS3/qspi1_cs[1]/VIN1a_clk0/VOUT3_clk/qspi2_cs[0]/GPMC_a[1]/gpio2_21/GPMC_a[24__gpmc_a[14)
N23578162: R501.1 U52.N7(GPMC_A08/qspi2_d[3]/VIN1a_hsync0/VOUT3_hsync/usb4_ulpi_nxt/VIN1b_hsync1/timer12/spi4_sclk/gpio1_30)
N23578164: R497.1 U52.N9(GPMC_A10/qspi2_d[1]/VIN1a_de0/VOUT3_de/usb4_ulpi_stp/VIN1b_clk1/timer10/spi4_d[0]/gpio2_0)
N23578166: R502.1 U52.P9(GPMC_A11/qspi2_d[0]/VIN1a_fld0/VOUT3_fld/VIN2a_fld0/usb4_ulpi_clk/VIN1b_de1/timer9/spi4_cs[0]/gpio2_1)
N23578168: R493.1 U52.R4(GPMC_A09/qspi2_d[2]/VIN1a_vsync0/VOUT3_vsync/usb4_ulpi_dir/VIN1b_vsync1/timer11/spi4_d[1]/gpio1_31)
N23578170: R495.1 U52.J7(GPMC_A23/mmc2_clk/GPMC_a[17]/VIN2a_fld0/VIN2b_d[4]/gpio2_13)
N23578180: R160.1 U52.R6(GPMC_A00/VIN1a_d[16]/VOUT3_d[16]/VIN2a_d[0]/usb4_ulpi_d7/VIN1b_d[0]/i2c4_scl/uart5_rxd/gpio7_3/GPMC_a[26]__gpmc_a[16])
N23578182: R504.1 U52.T6(GPMC_A02/VIN1a_d[18]/VOUT3_d[18]/VIN2a_d[2]/usb4_ulpi_d5/VIN1b_d[2]/uart7_rxd/uart5_ctsn/gpio7_5)
N23578184: R505.1 U52.T7(GPMC_A03/qspi1_cs[2]/VIN1a_d[19]/VOUT3_d[19]/VIN2a_d[3]/usb4_ulpi_d4/VIN1b_d[3]/uart7_txd/uart5_rtsn/gpio7_6)
N23578198: R507.1 U52.T9(GPMC_A01/VIN1a_d[17]/VOUT3_d[17]/VIN2a_d[1]/usb4_ulpi_d6/VIN1b_d[1]/i2c4_sda/uart5_txd/gpio7_4)
N23578972: R586.2 U52.D11(VOUT1_CLK/VIN2a_fld0/VIN1a_fld0/spi3_cs[0]/gpio4_19)
N23578974: R582.2 U52.C11(VOUT1_HSYNC/VIN2a_hsync0/VIN1a_hsync0/spi3_d[0]/gpio4_22)
N23578976: R595.2 U52.E11(VOUT1_VSYNC/VIN2a_vsync0/VIN1a_vsync0/spi3_sclk/pr2_pru1_pru_r31[17]/pr2_pru1_pru_r30[17]/gpio4_23)
N23578978: R212.2 U52.B10(VOUT1_DE/VIN2a_de0/VIN1a_de0/spi3_d[1]/gpio4_20)
N23579357: TP50.1 U52.B11(VOUT1_FLD/VIN2a_clk0/VIN1a_clk0/spi3_cs[1]/gpio4_21)
N23579375: R598.2 U52.F11(VOUT1_D00/uart5_rxd/VIN2a_d[16]/VIN1a_d[16]/spi3_cs[2]/pr1_uart0_cts_n/pr2_pru1_pru_r31[18]/pr2_pru1_pru_r30[18]/gpio8_0)
N23579377: R213.2 U52.G10(VOUT1_D01/uart5_txd/VIN2a_d[17]/VIN1a_d[17]/pr1_uart0_rts_n/pr2_pru1_pru_r31[19]/pr2_pru1_pru_r30[19]/gpio8_1)
N23579379: R217.2 U52.F10(VOUT1_D02/emu2/VIN2a_d[18]/VIN1a_d[18]/obs0/obs16/obs_irq1/pr1_uart0_rxd/pr2_pru1_pru_r31[20]/pr2_pru1_pru_r30[20]/gpio8_2)
N23579381: R218.2 U52.G11(VOUT1_D03/emu5/VIN2a_d[19]/VIN1a_d[19]/obs1/obs17/obs_dmarq1/pr1_uart0_txd/pr2_pru0_pru_r31[0]/pr2_pru0_pru_r30[0]/gpio8_3)
N23579383: R572.2 U52.E9(VOUT1_D04/emu6/VIN2a_d[20]/VIN1a_d[20]/obs2/obs18/pr1_ecap0_ecap_capin_apwm_o/pr2_pru0_pru_r31[1]/pr2_pru0_pru_r30[1]/gpio8_4)
N23579385: R556.2 U52.F9(VOUT1_D05/emu7/VIN2a_d[21]/VIN1a_d[21]/obs3/obs19/pr2_edc_latch0_in/pr2_pru0_pru_r31[2]/pr2_pru0_pru_r30[2]/gpio8_5)
N23579387: R564.2 U52.F8(VOUT1_D06/emu8/VIN2a_d[22]/VIN1a_d[22]/obs4/obs20/pr2_edc_latch1_in/pr2_pru0_pru_r31[3]/pr2_pru0_pru_r30[3]/gpio8_6)
N23579389: R542.2 U52.E7(VOUT1_D07/emu9/VIN2a_d[23]/VIN1a_d[23]/pr2_edc_sync0_out/pr2_pru0_pru_r31[4]/pr2_pru0_pru_r30[4]/gpio8_7)
N23579407: R544.2 U52.E8(VOUT1_D08/uart6_rxd/VIN2a_d[8]/VIN1a_d[8]/pr2_edc_sync1_out/pr2_pru0_pru_r31[5]/pr2_pru0_pru_r30[5]/gpio8_8)
N23579409: R563.2 U52.D9(VOUT1_D09/uart6_txd/VIN2a_d[9]/VIN1a_d[9]/pr2_edio_latch_in/pr2_pru0_pru_r31[6]/pr2_pru0_pru_r30[6]/gpio8_9)
N23579411: R551.2 U52.D7(VOUT1_D10/emu3/VIN2a_d[10]/VIN1a_d[10]/obs5/obs21/obs_irq2/pr2_edio_sof/pr2_pru0_pru_r31[7]/pr2_pru0_pru_r30[7]/gpio8_10)
N23579413: R545.2 U52.D8(VOUT1_D11/emu10/VIN2a_d[11]/VIN1a_d[11]/obs6/obs22/obs_dmarq2/pr2_uart0_cts_n/pr2_pru0_pru_r31[8]/pr2_pru0_pru_r30[8]/gpio8_11)
N23579415: R188.2 U52.A5(VOUT1_D12/emu11/VIN2a_d[12]/VIN1a_d[12]/obs7/obs23/pr2_uart0_rts_n/pr2_pru0_pru_r31[9]/pr2_pru0_pru_r30[9]/gpio8_12)
N23579417: R552.2 U52.C6(VOUT1_D13/emu12/VIN2a_d[13]/VIN1a_d[13]/obs8/obs24/pr2_uart0_rxd/pr2_pru0_pru_r31[10]/pr2_pru0_pru_r30[10]/gpio8_13)
N23579419: R550.2 U52.C8(VOUT1_D14/emu13/VIN2a_d[14]/VIN1a_d[14]/obs9/obs25/pr2_uart0_txd/pr2_pru0_pru_r31[11]/pr2_pru0_pru_r30[11]/gpio8_14)
N23579421: R557.2 U52.C7(VOUT1_D15/emu14/VIN2a_d[15]/VIN1a_d[15]/obs10/obs26/pr2_ecap0_ecap_capin_apwm_o/pr2_pru0_pru_r31[12]/pr2_pru0_pru_r30[12]/gpio8_15)
N23579439: R189.2 U52.B7(VOUT1_D16/uart7_rxd/VIN2a_d[0]/VIN1a_d[0]/pr2_edio_data_in0/pr2_edio_data_out0/pr2_pru0_pru_r31[13]/pr2_pru0_pru_r30[13]/gpio8_16)
N23579441: R199.2 U52.B8(VOUT1_D17/uart7_txd/VIN2a_d[1]/VIN1a_d[1]/pr2_edio_data_in1/pr2_edio_data_out1/pr2_pru0_pru_r31[14]/pr2_pru0_pru_r30[14]/gpio8_17)
N23579443: R197.2 U52.A7(VOUT1_D18/emu4/VIN2a_d[2]/VIN1a_d[2]/obs11/obs27/pr2_edio_data_in2/pr2_edio_data_out2/pr2_pru0_pru_r31[15]/pr2_pru0_pru_r30[15]/gpio8_18)
N23579445: R198.2 U52.A8(VOUT1_D19/emu15/VIN2a_d[3]/VIN1a_d[3]/obs12/obs28/pr2_edio_data_in3/pr2_edio_data_out3/pr2_pru0_pru_r31[16]/pr2_pru0_pru_r30[16]/gpio8_19)
N23579447: R571.2 U52.C9(vout1_d20/emu16/obs13/obs29/gpio8_20)
N23579449: R203.2 U52.A9(VOUT1_D21/emu17/VIN2a_d[5]/VIN1a_d[5]/obs14/obs30/pr2_edio_data_in5/pr2_edio_data_out5/pr2_pru0_pru_r31[18]/pr2_pru0_pru_r30[18]/gpio8_21)
N23579451: R202.2 U52.B9(VOUT1_D22/emu18/VIN2a_d[6]/VIN1a_d[6]/obs15/obs31/pr2_edio_data_in6/pr2_edio_data_out6/pr2_pru0_pru_r31[19]/pr2_pru0_pru_r30[19]/gpio8_22)
N23579453: R220.2 U52.A10(VOUT1_D23/emu19/VIN2a_d[7]/VIN1a_d[7]/spi3_cs[3]/pr2_edio_data_in7/pr2_edio_data_out7/pr2_pru0_pru_r31[20]/pr2_pru0_pru_r30[20]/gpio8_23)
N23580001: R547.2 U52.D5(VIN2A_D12/RGMII1_txc/VOUT2_d[11]/gmii1_rxd[7]/mii1_rxclk/kbd_col8/eCAP2_in_PWM2_out/pr1_mii1_txd1/pr1_pru1_pru_r31[9]/pr1_pru1)
N23580003: R543.2 U52.C4(VIN2A_D15/RGMII1_txd[2]/VOUT2_d[8]/gmii1_txd[0]/mii1_txd[0]/eQEP3_index/pr1_mii1_rxdv/pr1_pru1_pru_r31[12]/pr1_pru1_pru_r30[12)
N23580212: R173.2 U52.E1(VIN2A_CLK0/VOUT2_fld/emu5/kbd_row0/eQEP1A_in/pr1_edio_data_in0/pr1_edio_data_out0/gpio3_28/GPMC_a[27]__gpmc_a[17])
N23580264: R174.2 U52.C2(VIN2A_D13/RGMII1_txctl/VOUT2_d[10]/gmii1_rxdv/mii1_rxdv/kbd_row8/eQEP3A_in/pr1_mii1_txd0/pr1_pru1_pru_r31[10]/pr1_pru1_pru_r30)
N23580266: R176.2 U52.C3(VIN2A_D14/RGMII1_txd[3]/VOUT2_d[9]/gmii1_gtxclk/mii1_txclk/eQEP3B_in/pr1_mii_mr1_clk/pr1_pru1_pru_r31[11]/pr1_pru1_pru_r30[11])
N23580268: R175.2 U52.B2(VIN2A_D16/VIN2b_d[7]/RGMII1_txd[1]/VOUT2_d[7]/gmii1_txd[1]/mii1_txd[1]/eQEP3_strobe/pr1_mii1_rxd3/pr1_pru1_pru_r31[13]/pr1_pru)
N23580270: R546.2 U52.D6(VIN2A_D17/VIN2b_d[6]/RGMII1_txd[0]/VOUT2_d[6]/gmii1_txd[2]/mii1_txd[2]/ehrpwm3A/pr1_mii1_rxd2/pr1_pru1_pru_r31[14]/pr1_pru1_pr)
N28915304: R653.2 U52.D24(EMU1)
N28915306: R627.2 U52.G21(EMU0)

Not connected (* = marked no-connect by the designer): J17 10(EXTE)* 11(EXTF)* 14(TR_CLK1)* 18(TRD1.0)* 20(TRD1.1)* 22(TRD1.2)* 24(TRD1.3)* 26(TRD1.4)* 28(TRD1.5)* 30(TRD1.6)* 32(TRD1.7)* 34(TRD1.8)* 36(TRD1.9)* 38(TRD2.0)* 40(TRD2.1)* 42(TRD2.2)* 44(TRD2.3)* 46(TRD2.4)* 48(TRD2.5)* 50(TRD2.6)* 52(TRD2.7)* 54(TRD2.8)* 55(TRD3.9)* 56(TRD2.9)* 59(TR_CLK3)* 60(TR_CLK2)*; P8 4 5 7 8 12 13 14 15 18 20 21 22 23 26 27 28 29 30 31 32 36; U52 AD3(NC) AD8(NC) AD9(NC) AE3(NC) AE5(NC) AE6(NC) AE8(NC) AE9(NC) AF4(NC) AF6(NC) AF8(NC) AF9(NC) AG2(NC) AG8(NC) E26(NC) E27(NC) E28(NC) F24(NC) F25(NC) F26(NC) F27(NC) F28(NC) G24(NC) G25(NC) G26(NC) G27(NC) G28(NC) H23(NC) H24(NC) H25(NC) H26(NC) H27(NC) H28(NC) J20(NC) J23(NC) J24(NC) J25(NC) J26(NC) K20(NC) K21(NC) K22(NC) K23(NC) K27(NC) K28(NC) L22(NC) L23(NC) L24(NC) L25(NC) L26(NC) L27(NC) L28(NC) M22(NC) M23(NC) M24(NC) M25(NC) M26(NC) M27(NC) M28(NC) N20(NC) N22(NC) N23(NC) N27(NC) N28(NC) P22(NC) P23(NC) P24(NC) P25(NC) P26(NC) P27(NC) R22(NC) R23(NC) R24(NC) R25(NC) R26(NC) R27(NC) R28(NC) T22(NC) T23(NC) T27(NC) T28(NC) U22(NC) U23(NC) U24(NC) U25(NC) U26(NC) U27(NC) U28(NC)

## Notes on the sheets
sheet 1
- SH01 - TITLE PAGE
  SH02 - SoC MCASP
  SH03 - SoC SERIAL I/O
  SH04 - SoC SD/MMC IF
  SH05 - SoC MLB
  SH06 - SoC ETHERNET/USB
  SH07 - SoC GPMC
  SH08 - SoC DDR EMIF1 INTERFACE
  SH09 - SoC DDR EMIF2 NC
  SH10 - SoC HDMI
  SH11 - SoC VOUT1 PORT LCD
  SH12 - SoC VIDEO PORTS IN
  SH13 - SoC SATA/PCIe INTERFACE
  SH14 - SoC JTAG
  SH15 - SoC CLOCKS
  SH16 - SoC INTERNAL LDOS
  SH17 - SoC IO POWER
  SH18 - SoC POWER 1V8
  SH19 - SoC DDR POWER
  SH20 - SoC 1V8A
  SH21 - SoC CORE POWER
  SH22 - SoC GROUND PINS
  SH23 - DDR3 EMIF1 TESTPOINTS
  SH24 - DDR3 BANK 1 ECC
  SH25 - DDR3 MEMORY BANK 1
  SH26 - DDR3 MEMORY CAPS BANK 1
  SH27 - DDR TERMNATION BANK 1
  SH28 - MUX A/C QSPI/EMMC/GPMX
  SH29 - MUX B VOUT3/GPMC
  SH30 - MUX B VOUT3/GPMC ADD
  SH31 - MUX D GMPCA
  SH32 - MUX E VIN2
  SH33 - MUX G ENET0/VIN4
  SH34 - MUX H MCASP/VIN6A
  SH35 - MUX J/K/L SERIAL I/O
  SH36 - MEM SPI FLASH
  SH37 - MEM NAND FLASH
  SH38 - MEM NOR FLASH
  SH39 - MEM eMMC
  SH40 - MEM SD CARD
  SH41 - USB VBUS
  SH42 - USB CONNECTORS
  SH43 - USB FTDI UART
  SH44 - AIC3106
  SH45 - SERDES CLOCK
  SH46 - PCIe CONNECTORS
  SH47 - LCD CONNECTOR
  SH48 - HDMI OUTPUT CONNECTOR
  SH49 - FPD LINK
  SH50 - CAMERA IF
  SH51 - CAN CONNECTORS
  SH52 - I2C EEPROM/TEMP SENSOR
  SH53 - I2C EXPANDER
  SH54 - BOOTSWITCHES
  SH55 - COM8 LEVEL TRANSLATOR
  SH56 - COM8 CONNECTOR
  SH57 - ETHERNET POWER AND RESET
  SH58 - ETHERNET PORT0
  SH59 - ETHERNET PORT1
  SH60 - APPLICATION IF CONN1
  SH61 - APPLICATION IF  CONN2
  SH62 - APPLICATION IF  CONN3
  SH63 - RESET
  SH64 - POWER INPUT
  SH65 - POWER TPS443351DAP
  SH66 - MISC POWER SWITCHES
  SH67 - PMIC
  SH68 - POWER MONITOR 1
  SH69 - POWER MONITOR 2
  SH70 - DARA
  SH71 - ECN REV B1 TO C
- REVISION STATUS OF SHEETS
- REV
- SH
- REV
- SH
- REV
- D
- SH
- 71
- REV
- C
- C
- A
- C
- C
- C
- D
- C
- C
- C
- SH
- 61
- 62
- 63
- 64
- 65
- 66
- 67
- 68
- 69
- 70
- REV
- A
- C2
- A
- A
- A
- A
- C
- D
- D
- C
- SH
- 51
- 52
- 53
- 54
- 55
- 56
- 57
- 58
- 59
- 60
- REV
- A
- B
- A
- A
- A
- B
- A
- C
- A
- B
- SH
- 41
- 42
- 43
- 44
- 45
- 46
- 47
- 48
- 49
- 50
- REV
- A
- D
- C
- A
- A
- A
- A
- A
- C
- C
- DWN
- DATE
- SH
- 31
- 32
- 33
- 34
- 35
- 36
- 37
- 38
- 39
- 40
- J.A.C.
- 11/12/2015
- REV
- A
- A
- B
- C
- C
- A
- C
- A
- C
- C
- CHK
- T.W.K.
- 11/12/2015
- DATE
- ENGR
- DATE
- SH
- 21
- 22
- 23
- 24
- 25
- 26
- 27
- 28
- 29
- 30
- J.A.C.
- 11/12/2015
- ENGR-MGR
- DATE
- REV
- D
- A
- C
- C
- A
- A
- A
- A
- A
- D2
- J.A.C.
- 11/12/2015
- SH
- 11
- 12
- 13
- 14
- 15
- 16
- 17
- 18
- 19
- 20
- QA
- C.M.D.
- 11/12/2015
- DATE
- MFG
- DATE
- REV
- D
- A
- C
- A
- A
- A
- A
- B
- A
- C
- NEXT ASSY
- USED ON
- J.A.C.
- 11/12/2015
- RLSE
- DATE
- SH
- 1
- 2
- 3
- 4
- 5
- 6
- 7
- 8
- 9
- 10
- APPLICATION
- J.A.C.
- 11/12/2015
sheet 3
- PLACE 100 OHM RESISTORS AT CPU
- 100 ohm diff pairs
- GP1[5] REPLACED
sheet 4
- AQSPI PATH IS THE FAST PATH WITH MAX TRACE LENGTH OF
  2.75 INCHES.  THIS RESISTOR POPULATIONS IS ON BOTH
  ENDS OF THE NET.  THE OTHER END IS THE SPI FLASH U18.
sheet 5
- EACH DATA GROUP IS MATCHED WITHIN
  THE GROUP.  SEE PCB GUIDELINES FOR
  SPECIFIC RULES.
- differential pairs 100 ohm
- 6 places
- Data Group 0-0
- Data Group 0-1
- Data Group 0-2
- Data Group 0-3
sheet 7
- 1.8 VOLT
- ER5
sheet 8
- 22 OHM OK FOR LCD AS IT IS NOT GOING THROUGH MUXES.
- LCD_B2 = EMU2 TRACE CLOCK
sheet 9
- 100 OHM DIFF, S/2S/3S SPACING RULES
- CSI2_0 GROUP
- CSI2_1 GROUP
sheet 10
- ER8
- TRSTn ==  MIPI TRSTPD PULL DOWN VERSION
  TRSTn ==  MIPI nTRST MIPI PULLUP VERSION
  FOR CJTAG REMOVE R761 AND POPULATE R760,
  AS CTJAG NEEDS THE PULLUP VERSION.
- EMUx SIGNALS NEED TO ROUTE FROM U52
  THROUGH J17/J14 THEN TO LCD.  THE TRACE
  LENGTH RULES FOR THE LCD SIGNALS NEEDS
  TO BE MAINTAINED.
